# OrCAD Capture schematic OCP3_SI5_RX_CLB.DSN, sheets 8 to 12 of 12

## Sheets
8 PAGE08: size Custom
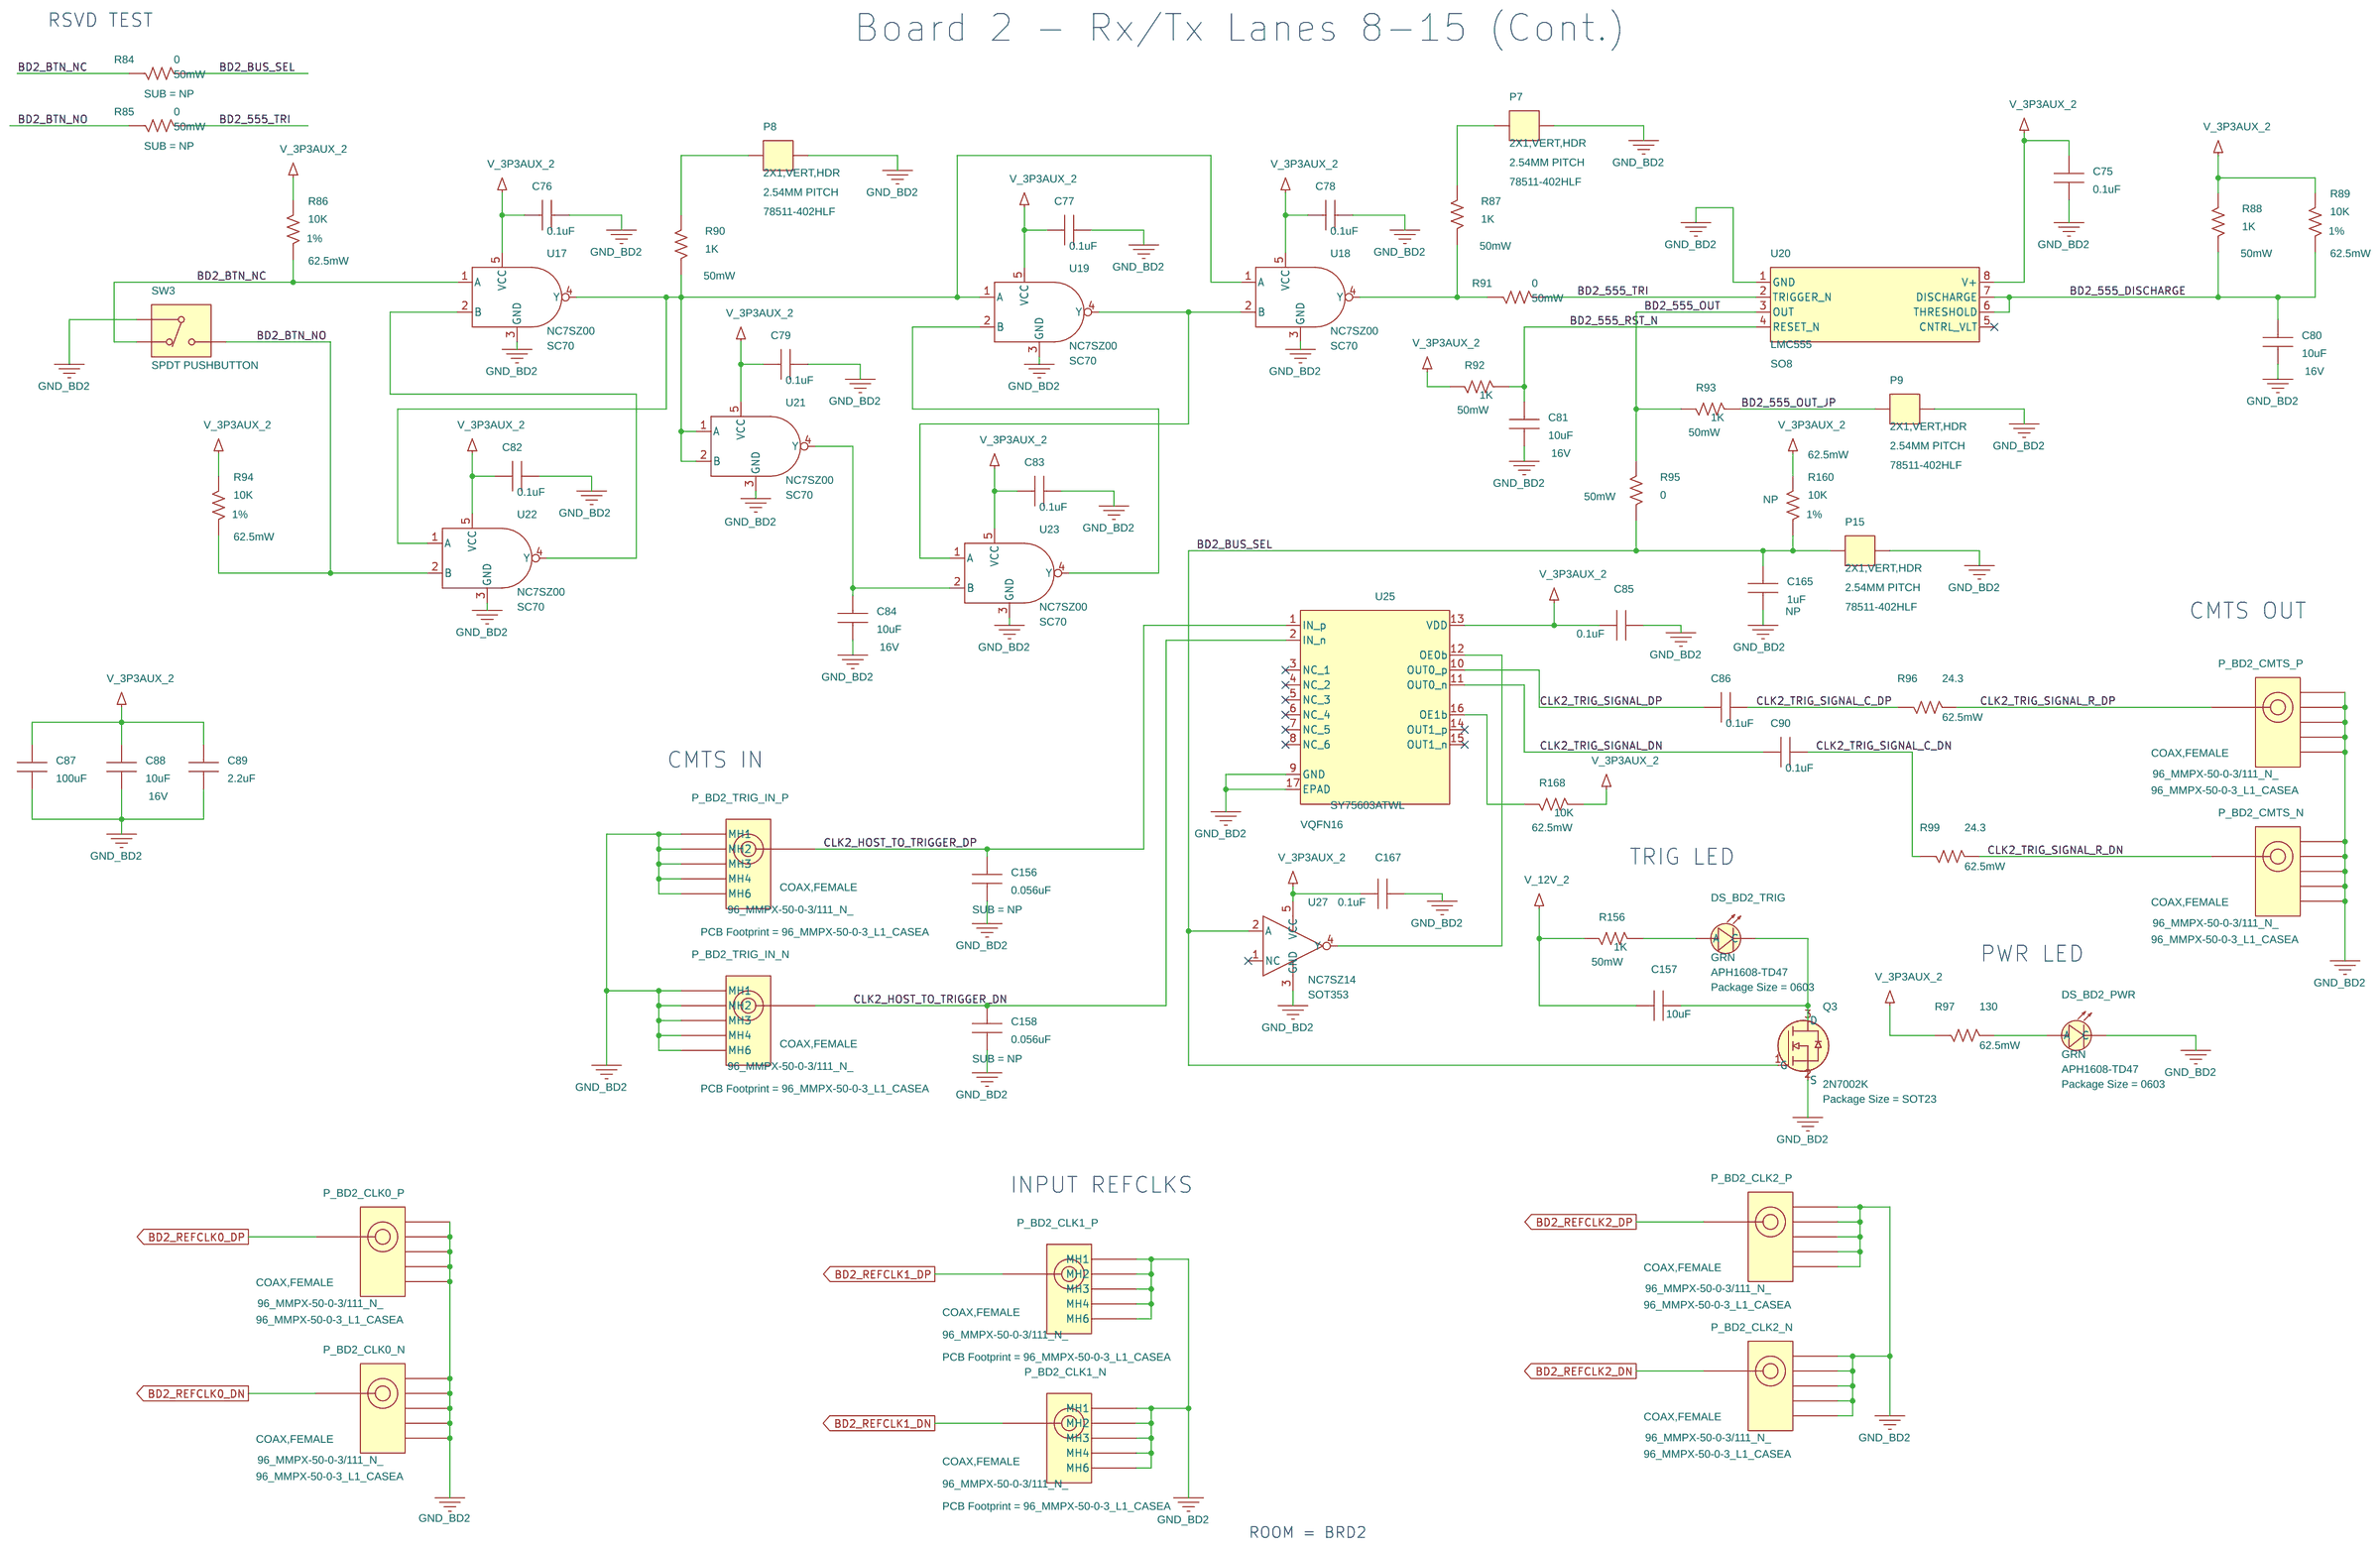
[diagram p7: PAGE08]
9 PAGE09: size Custom
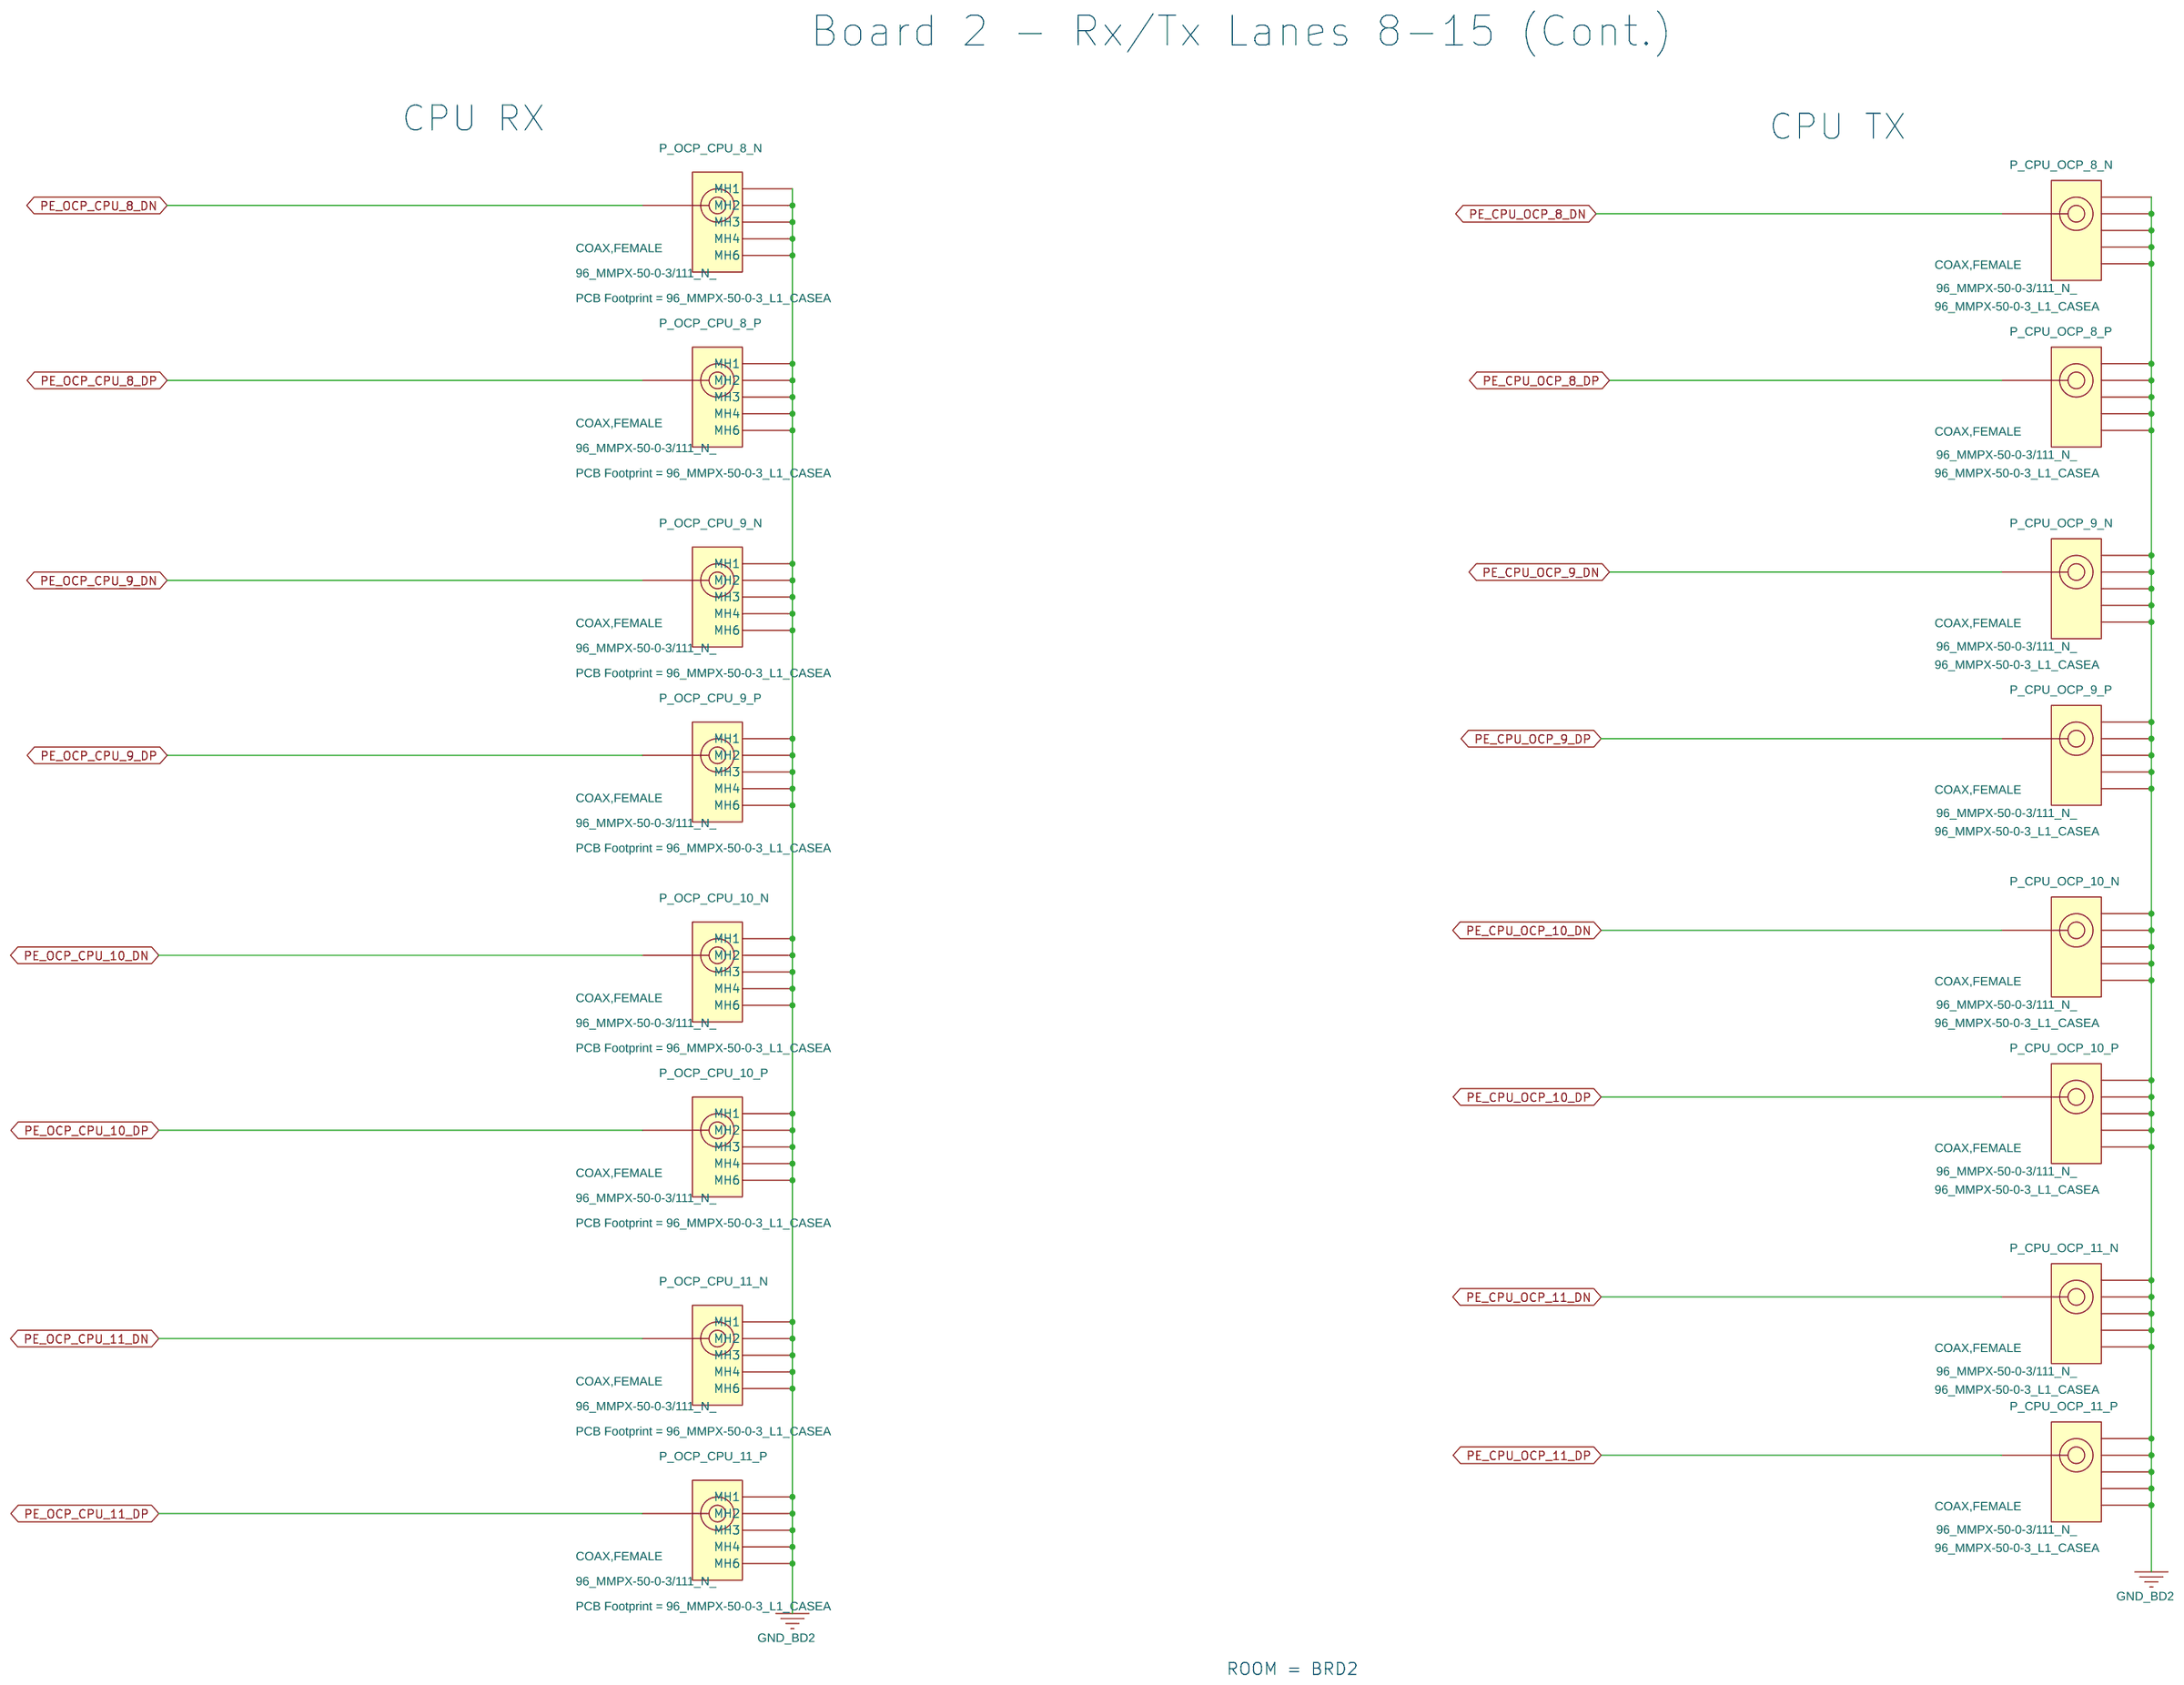
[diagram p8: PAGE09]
10 PAGE10: size Custom
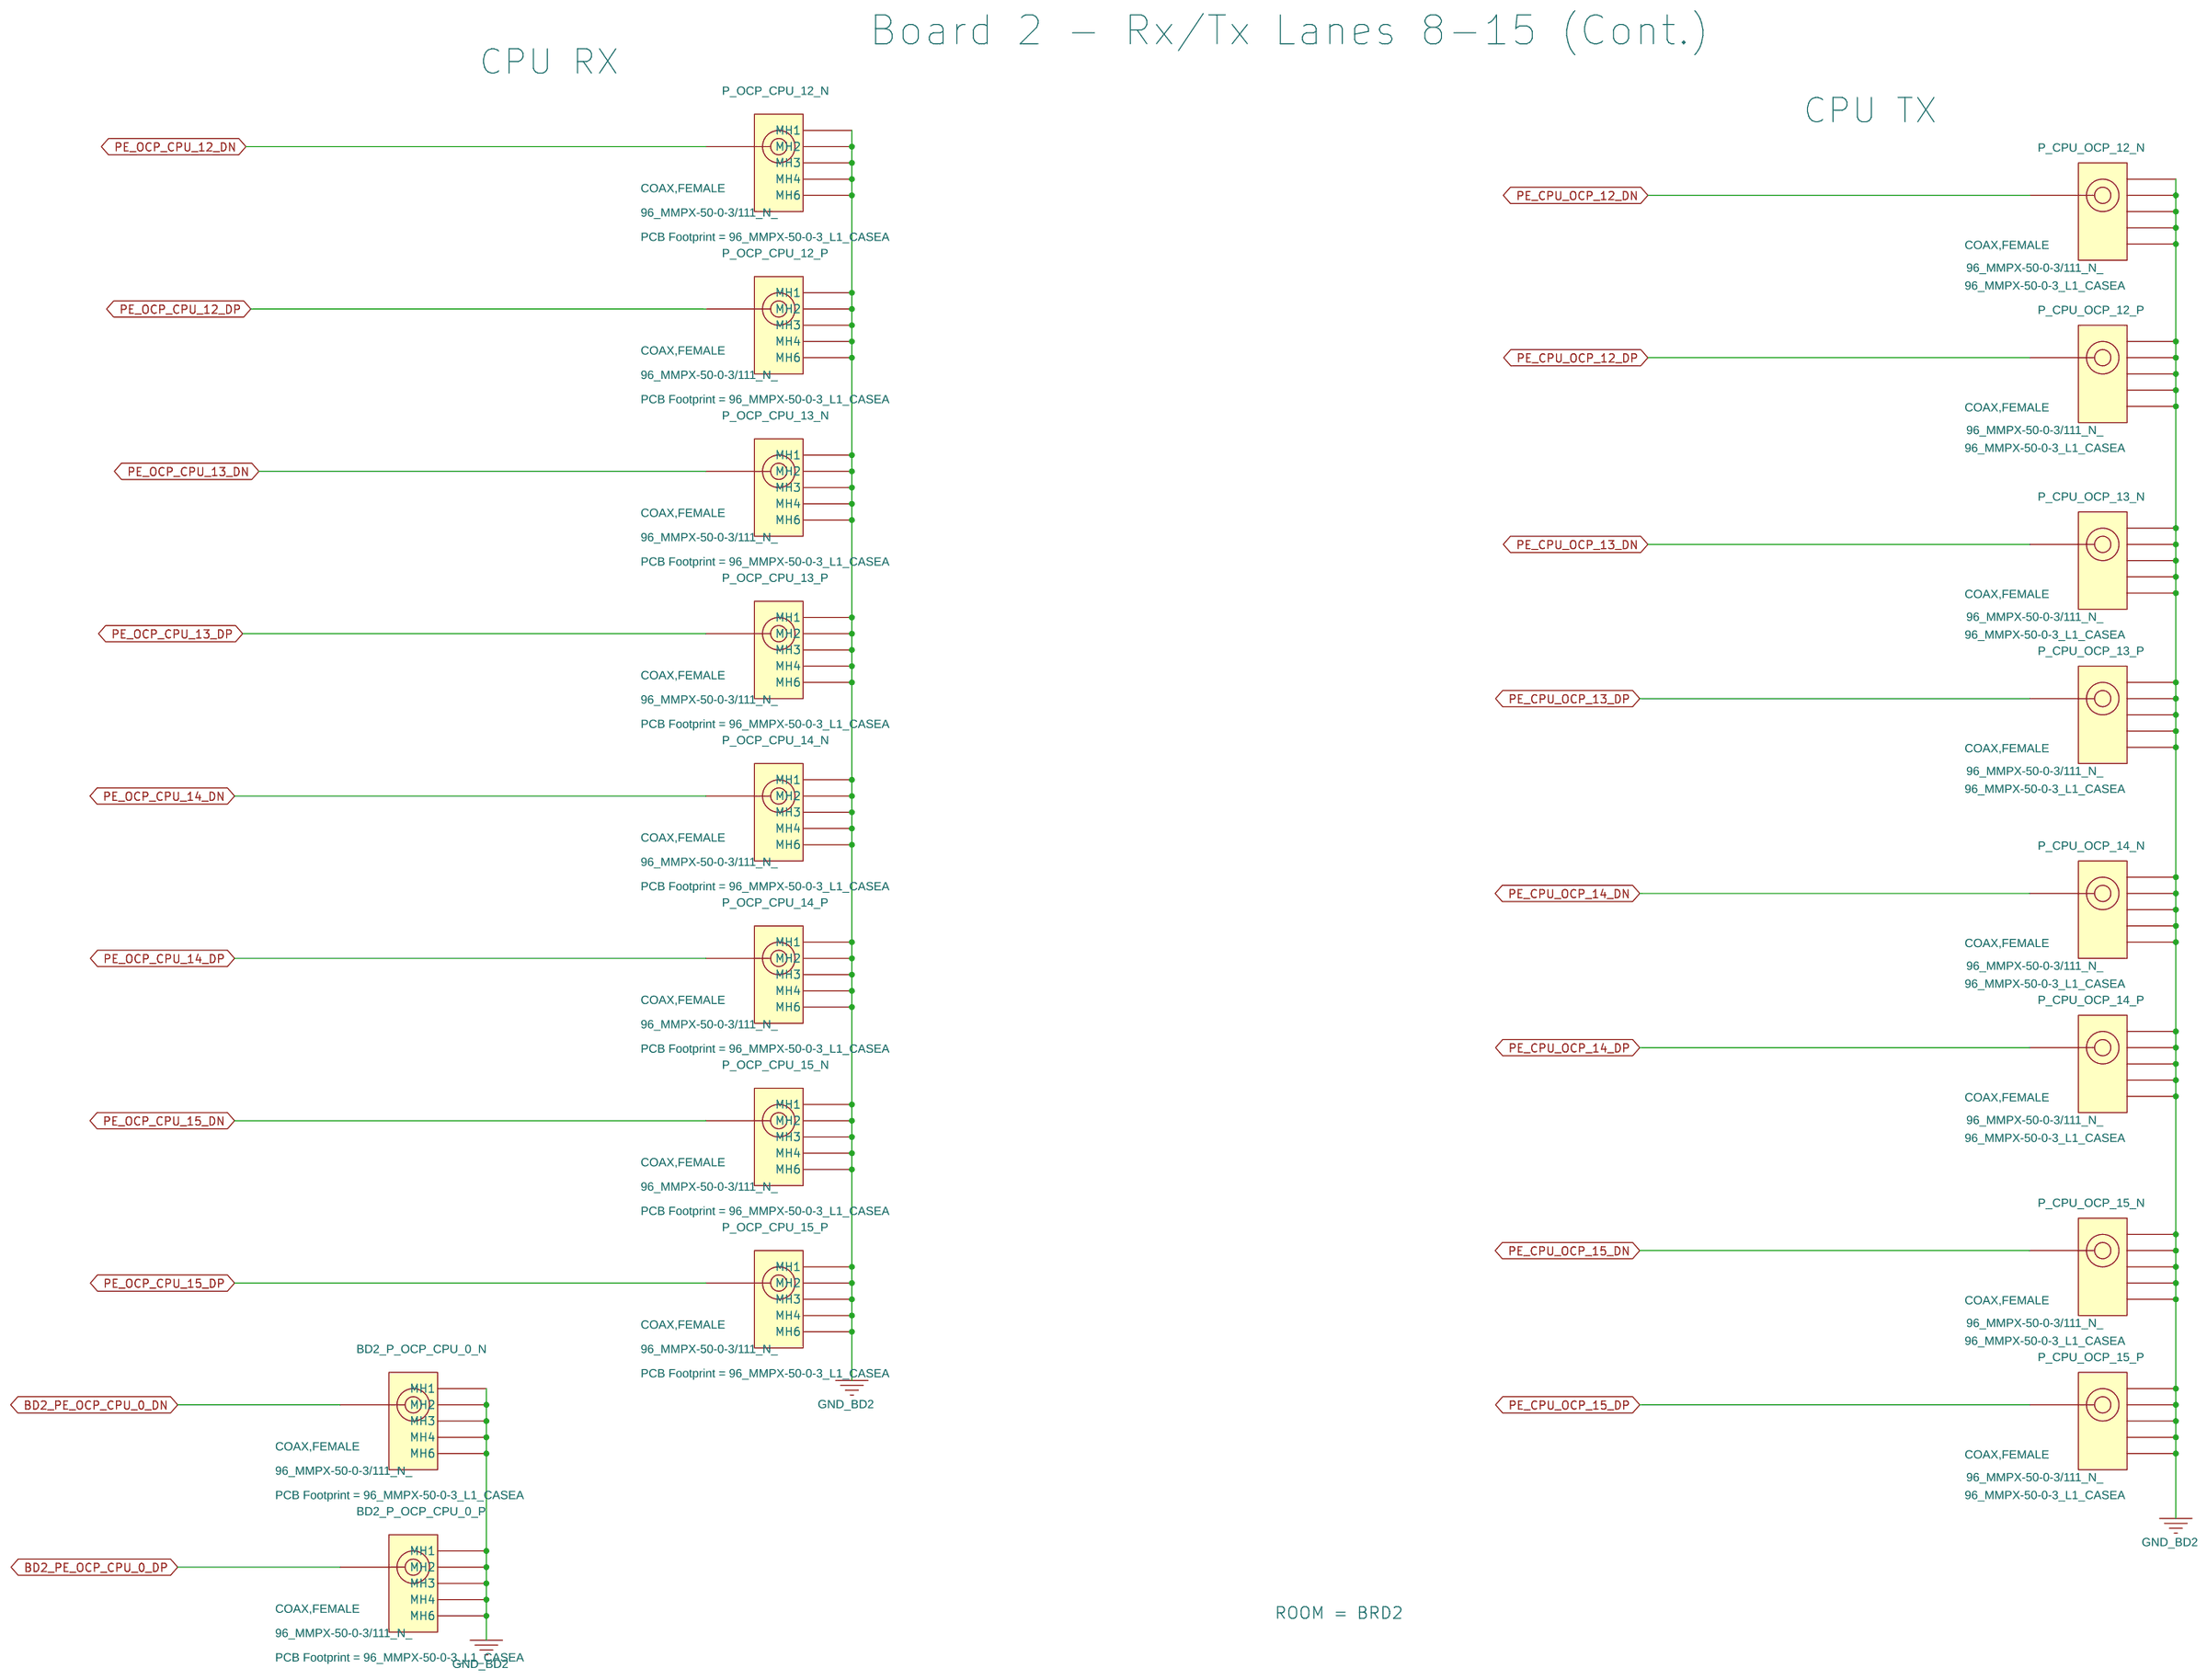
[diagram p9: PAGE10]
11 PAGE11: size Custom
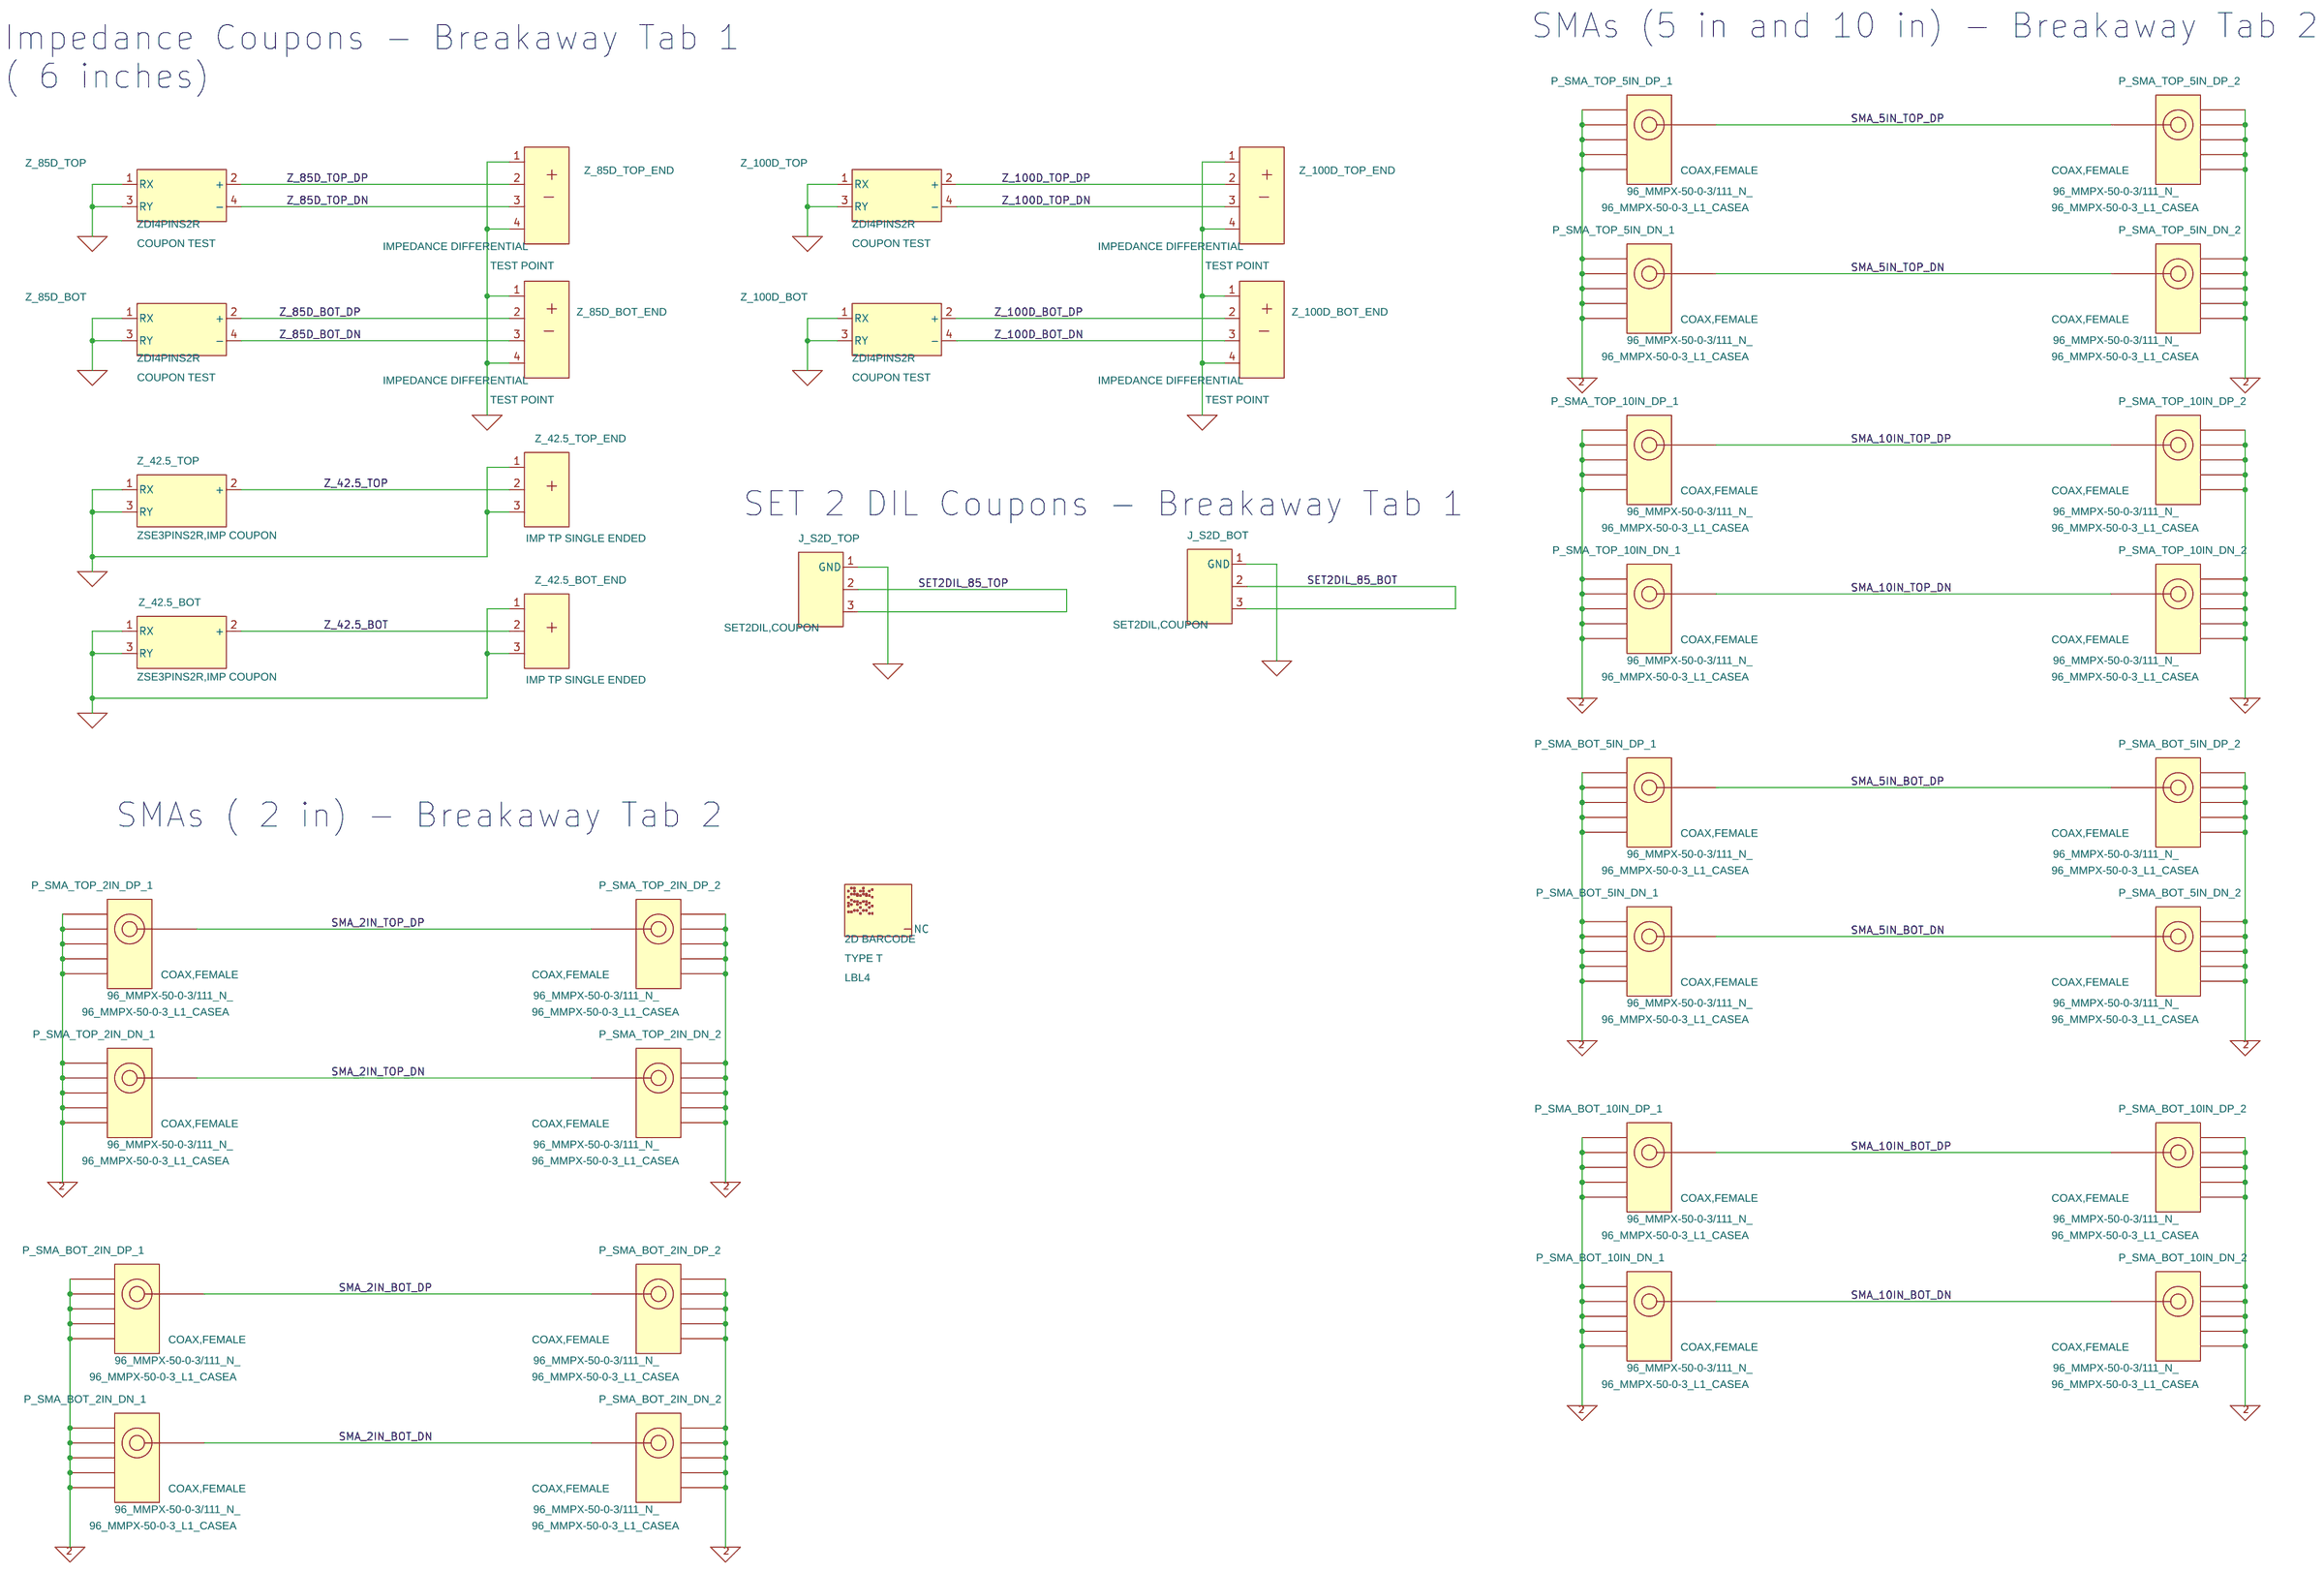
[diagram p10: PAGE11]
12 PAGE12: size Custom
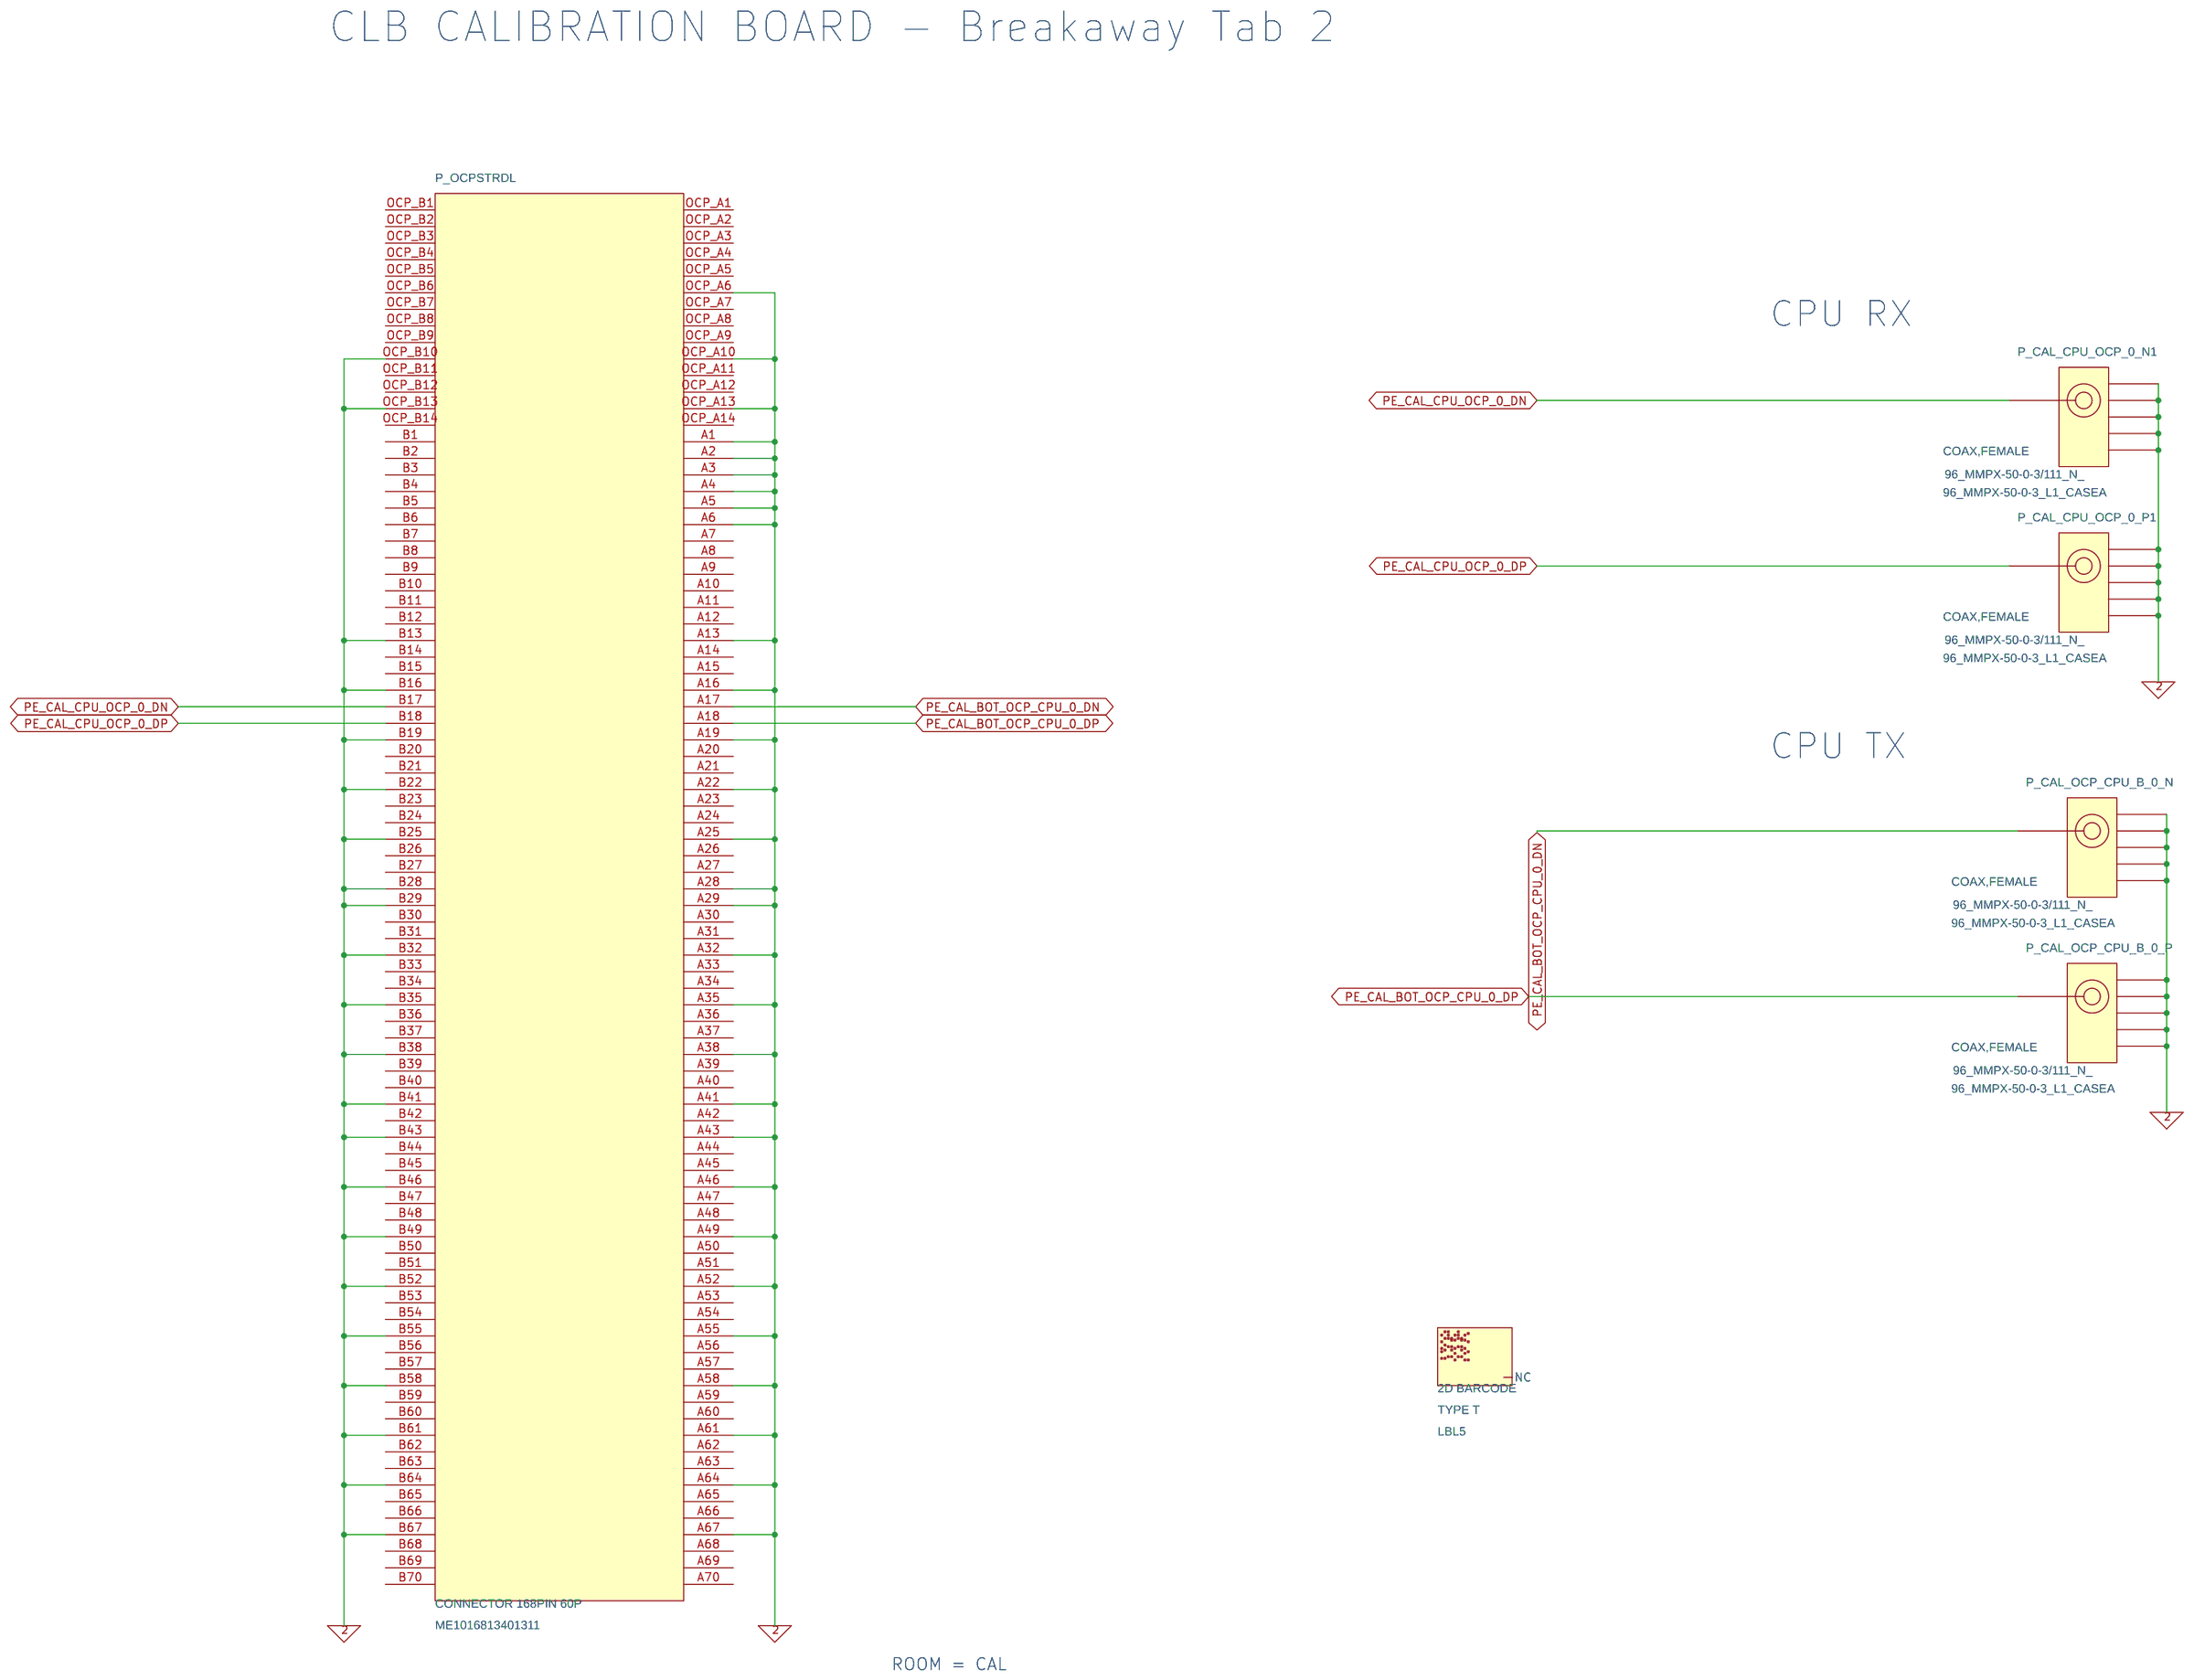
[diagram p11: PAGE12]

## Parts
sheet PAGE08
C75  0.1uF  [C0201]
C76  0.1uF  [C0201]
C77  0.1uF  [C0201]
C78  0.1uF  [C0201]
C79  0.1uF  [C0201]
C80  10uF  [C0603]
C81  10uF  [C0603]
C82  0.1uF  [C0201]
C83  0.1uF  [C0201]
C84  10uF  [C0603]
C85  0.1uF  [C0201]
C86  0.1uF  [C0201]
C87  100uF  [C1210_107H]
C88  10uF  [C0603]
C89  2.2uF  [C0603]
C90  0.1uF  [C0201]
C156  0.056uF  [C0402]
C157  10uF  [C0603]
C158  0.056uF  [C0402]
C165  1uF  [C0603]
C167  0.1uF  [C0201]
DS_BD2_PWR  APH1608-TD47  [LEDC1608X65N]
DS_BD2_TRIG  APH1608-TD47  [LEDC1608X65N]
P7  2X1,VERT,HDR  [BERG1X2]
P8  2X1,VERT,HDR  [BERG1X2]
P9  2X1,VERT,HDR  [BERG1X2]
P15  2X1,VERT,HDR  [BERG1X2]
P_BD2_CLK0_N  COAX,FEMALE  [96_MMPX-50-0-3_L1_CASEA]
P_BD2_CLK0_P  COAX,FEMALE  [96_MMPX-50-0-3_L1_CASEA]
P_BD2_CLK1_N  COAX,FEMALE  [96_MMPX-50-0-3_L1_CASEA]
P_BD2_CLK1_P  COAX,FEMALE  [96_MMPX-50-0-3_L1_CASEA]
P_BD2_CLK2_N  COAX,FEMALE  [96_MMPX-50-0-3_L1_CASEA]
P_BD2_CLK2_P  COAX,FEMALE  [96_MMPX-50-0-3_L1_CASEA]
P_BD2_CMTS_N  COAX,FEMALE  [96_MMPX-50-0-3_L1_CASEA]
P_BD2_CMTS_P  COAX,FEMALE  [96_MMPX-50-0-3_L1_CASEA]
P_BD2_TRIG_IN_N  COAX,FEMALE  [96_MMPX-50-0-3_L1_CASEA]
P_BD2_TRIG_IN_P  COAX,FEMALE  [96_MMPX-50-0-3_L1_CASEA]
Q3  2N7002K  [SOT95P237X117_3N]
R84  0  [R0201]
R85  0  [R0201]
R86  10K  [R0402]
R87  1K  [R0201]
R88  1K  [R0201]
R89  10K  [R0402]
R90  1K  [R0201]
R91  0  [R0201]
R92  1K  [R0201]
R93  1K  [R0201]
R94  10K  [R0402]
R95  0  [R0201]
R96  24.3  [R0402]
R97  130  [R0402]
R99  24.3  [R0402]
R156  1K  [R0201]
R160  10K  [R0402]
R168  10K  [R0402]
SW3  SPDT PUSHBUTTON  [SW3PSMRA_2SH]
U17  NC7SZ00  [SOT65P210X110_5N]
U18  NC7SZ00  [SOT65P210X110_5N]
U19  NC7SZ00  [SOT65P210X110_5N]
U20  LMC555  [SOIC127P600X175_8N]
U21  NC7SZ00  [SOT65P210X110_5N]
U22  NC7SZ00  [SOT65P210X110_5N]
U23  NC7SZ00  [SOT65P210X110_5N]
U25  SY75603ATWL  [QFN50P300X300X90-17]
U27  NC7SZ14  [SOT65P210X110_5L]
sheet PAGE09
P_CPU_OCP_8_N  COAX,FEMALE  [96_MMPX-50-0-3_L1_CASEA]
P_CPU_OCP_8_P  COAX,FEMALE  [96_MMPX-50-0-3_L1_CASEA]
P_CPU_OCP_9_N  COAX,FEMALE  [96_MMPX-50-0-3_L1_CASEA]
P_CPU_OCP_9_P  COAX,FEMALE  [96_MMPX-50-0-3_L1_CASEA]
P_CPU_OCP_10_N  COAX,FEMALE  [96_MMPX-50-0-3_L1_CASEA]
P_CPU_OCP_10_P  COAX,FEMALE  [96_MMPX-50-0-3_L1_CASEA]
P_CPU_OCP_11_N  COAX,FEMALE  [96_MMPX-50-0-3_L1_CASEA]
P_CPU_OCP_11_P  COAX,FEMALE  [96_MMPX-50-0-3_L1_CASEA]
P_OCP_CPU_8_N  COAX,FEMALE  [96_MMPX-50-0-3_L1_CASEA]
P_OCP_CPU_8_P  COAX,FEMALE  [96_MMPX-50-0-3_L1_CASEA]
P_OCP_CPU_9_N  COAX,FEMALE  [96_MMPX-50-0-3_L1_CASEA]
P_OCP_CPU_9_P  COAX,FEMALE  [96_MMPX-50-0-3_L1_CASEA]
P_OCP_CPU_10_N  COAX,FEMALE  [96_MMPX-50-0-3_L1_CASEA]
P_OCP_CPU_10_P  COAX,FEMALE  [96_MMPX-50-0-3_L1_CASEA]
P_OCP_CPU_11_N  COAX,FEMALE  [96_MMPX-50-0-3_L1_CASEA]
P_OCP_CPU_11_P  COAX,FEMALE  [96_MMPX-50-0-3_L1_CASEA]
sheet PAGE10
BD2_P_OCP_CPU_0_N  COAX,FEMALE  [96_MMPX-50-0-3_L1_CASEA]
BD2_P_OCP_CPU_0_P  COAX,FEMALE  [96_MMPX-50-0-3_L1_CASEA]
P_CPU_OCP_12_N  COAX,FEMALE  [96_MMPX-50-0-3_L1_CASEA]
P_CPU_OCP_12_P  COAX,FEMALE  [96_MMPX-50-0-3_L1_CASEA]
P_CPU_OCP_13_N  COAX,FEMALE  [96_MMPX-50-0-3_L1_CASEA]
P_CPU_OCP_13_P  COAX,FEMALE  [96_MMPX-50-0-3_L1_CASEA]
P_CPU_OCP_14_N  COAX,FEMALE  [96_MMPX-50-0-3_L1_CASEA]
P_CPU_OCP_14_P  COAX,FEMALE  [96_MMPX-50-0-3_L1_CASEA]
P_CPU_OCP_15_N  COAX,FEMALE  [96_MMPX-50-0-3_L1_CASEA]
P_CPU_OCP_15_P  COAX,FEMALE  [96_MMPX-50-0-3_L1_CASEA]
P_OCP_CPU_12_N  COAX,FEMALE  [96_MMPX-50-0-3_L1_CASEA]
P_OCP_CPU_12_P  COAX,FEMALE  [96_MMPX-50-0-3_L1_CASEA]
P_OCP_CPU_13_N  COAX,FEMALE  [96_MMPX-50-0-3_L1_CASEA]
P_OCP_CPU_13_P  COAX,FEMALE  [96_MMPX-50-0-3_L1_CASEA]
P_OCP_CPU_14_N  COAX,FEMALE  [96_MMPX-50-0-3_L1_CASEA]
P_OCP_CPU_14_P  COAX,FEMALE  [96_MMPX-50-0-3_L1_CASEA]
P_OCP_CPU_15_N  COAX,FEMALE  [96_MMPX-50-0-3_L1_CASEA]
P_OCP_CPU_15_P  COAX,FEMALE  [96_MMPX-50-0-3_L1_CASEA]
sheet PAGE11
J_S2D_BOT  SET2DIL,COUPON  [TP3_PPROBEB]
J_S2D_TOP  SET2DIL,COUPON  [TP3_PPROBEB]
LBL4  2d_label500x437  [2D_LABEL500X437]
P_SMA_BOT_2IN_DN_1  COAX,FEMALE  [96_MMPX-50-0-3_L1_CASEA]
P_SMA_BOT_2IN_DN_2  COAX,FEMALE  [96_MMPX-50-0-3_L1_CASEA]
P_SMA_BOT_2IN_DP_1  COAX,FEMALE  [96_MMPX-50-0-3_L1_CASEA]
P_SMA_BOT_2IN_DP_2  COAX,FEMALE  [96_MMPX-50-0-3_L1_CASEA]
P_SMA_BOT_5IN_DN_1  COAX,FEMALE  [96_MMPX-50-0-3_L1_CASEA]
P_SMA_BOT_5IN_DN_2  COAX,FEMALE  [96_MMPX-50-0-3_L1_CASEA]
P_SMA_BOT_5IN_DP_1  COAX,FEMALE  [96_MMPX-50-0-3_L1_CASEA]
P_SMA_BOT_5IN_DP_2  COAX,FEMALE  [96_MMPX-50-0-3_L1_CASEA]
P_SMA_BOT_10IN_DN_1  COAX,FEMALE  [96_MMPX-50-0-3_L1_CASEA]
P_SMA_BOT_10IN_DN_2  COAX,FEMALE  [96_MMPX-50-0-3_L1_CASEA]
P_SMA_BOT_10IN_DP_1  COAX,FEMALE  [96_MMPX-50-0-3_L1_CASEA]
P_SMA_BOT_10IN_DP_2  COAX,FEMALE  [96_MMPX-50-0-3_L1_CASEA]
P_SMA_TOP_2IN_DN_1  COAX,FEMALE  [96_MMPX-50-0-3_L1_CASEA]
P_SMA_TOP_2IN_DN_2  COAX,FEMALE  [96_MMPX-50-0-3_L1_CASEA]
P_SMA_TOP_2IN_DP_1  COAX,FEMALE  [96_MMPX-50-0-3_L1_CASEA]
P_SMA_TOP_2IN_DP_2  COAX,FEMALE  [96_MMPX-50-0-3_L1_CASEA]
P_SMA_TOP_5IN_DN_1  COAX,FEMALE  [96_MMPX-50-0-3_L1_CASEA]
P_SMA_TOP_5IN_DN_2  COAX,FEMALE  [96_MMPX-50-0-3_L1_CASEA]
P_SMA_TOP_5IN_DP_1  COAX,FEMALE  [96_MMPX-50-0-3_L1_CASEA]
P_SMA_TOP_5IN_DP_2  COAX,FEMALE  [96_MMPX-50-0-3_L1_CASEA]
P_SMA_TOP_10IN_DN_1  COAX,FEMALE  [96_MMPX-50-0-3_L1_CASEA]
P_SMA_TOP_10IN_DN_2  COAX,FEMALE  [96_MMPX-50-0-3_L1_CASEA]
P_SMA_TOP_10IN_DP_1  COAX,FEMALE  [96_MMPX-50-0-3_L1_CASEA]
P_SMA_TOP_10IN_DP_2  COAX,FEMALE  [96_MMPX-50-0-3_L1_CASEA]
Z_42.5_BOT  ZSE3PINS2R,IMP COUPON  [ZSE3PINS2R]
Z_42.5_BOT_END  IMP TP SINGLE ENDED  [IMP_TP_1X3_35P]
Z_42.5_TOP  ZSE3PINS2R,IMP COUPON  [ZSE3PINS2R]
Z_42.5_TOP_END  IMP TP SINGLE ENDED  [IMP_TP_1X3_35P]
Z_85D_BOT  zdi4pins2r  [ZDI4PINS2R]
Z_85D_BOT_END  imp_tp_diff  [IMP_TP_1X4_35P]
Z_85D_TOP  zdi4pins2r  [ZDI4PINS2R]
Z_85D_TOP_END  imp_tp_diff  [IMP_TP_1X4_35P]
Z_100D_BOT  zdi4pins2r  [ZDI4PINS2R]
Z_100D_BOT_END  imp_tp_diff  [IMP_TP_1X4_35P]
Z_100D_TOP  zdi4pins2r  [ZDI4PINS2R]
Z_100D_TOP_END  imp_tp_diff  [IMP_TP_1X4_35P]
sheet PAGE12
LBL5  2d_label500x437  [2D_LABEL500X437]
P_CAL_CPU_OCP_0_N1  COAX,FEMALE  [96_MMPX-50-0-3_L1_CASEA]
P_CAL_CPU_OCP_0_P1  COAX,FEMALE  [96_MMPX-50-0-3_L1_CASEA]
P_CAL_OCP_CPU_B_0_N  COAX,FEMALE  [96_MMPX-50-0-3_L1_CASEA]
P_CAL_OCP_CPU_B_0_P  COAX,FEMALE  [96_MMPX-50-0-3_L1_CASEA]
P_OCPSTRDL  CONNECTOR 168PIN 60P  [AMP_STRDL_168PIN_60P]

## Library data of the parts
C75-C79 C82 C83 C85 C86 C90 C167 = cap: CAP,0.1UF,10%,10V,X5R,0201; ALT_SYMBOLS: (CAPC0603X33N,C0201M_FOX,C0201_R4); CLASS: DISCRETE; DPN: MNN3J; Dielectric Type: X5R; Lead Free: Yes; Lifecycle Phase: A Revision; Manufacturer: DARFON ELECTRONICS CORP; Manufacturer PN: C0603X5R104KDT; Package Height: 0.33 MM; Package Size: 0201; Package Type: SMD; Part Number: MNN3J; ROOM: BRD2; Rev: A00-00; Tolerance: 10%; Voltage: 10V
C80 C81 C84 C88 = cap: CAP,10UF,20%,16V,X6S,0603; CLASS: DISCRETE; DEVICE: 090729120217; DPN: 3MRV8; Dielectric Type: X6S; Lead Free: Yes; Lifecycle Phase: A Revision; Manufacturer: MURATA ERIE; Manufacturer PN: GRM188C81C106MA73D; Package Height: 40 MIL; Package Size: 0603; Package Type: SMD; Part Number: 3MRV8; ROOM: BRD2; Rev: A00-00; TOLERANCE: 20%; VOLTAGE: 16V
C87 = cap: CAP,100UF,20%,6.3V,X5R,1210; CLASS: DISCRETE; DPN: DN761; Dielectric Type: X5R; Lead Free: Yes; Lifecycle Phase: A Revision; Manufacturer: MURATA ERIE; Manufacturer PN: GRM32ER60J107ME20L; Package Height: 107 MIL; Package Size: 1210; Package Type: SMD; Part Number: DN761; ROOM: BRD2; Rev: A00-00; Tolerance: 20%; Voltage: 6.3V
C89 = cap: CAP,2.2UF,10%,16V,X5R,0603; CLASS: DISCRETE; DPN: J6201; Dielectric Type: X5R; Lead Free: Yes; Lifecycle Phase: A Revision; Manufacturer: MURATA ERIE; Manufacturer PN: GRM188R61C225KE15D; Package Height: 40 MIL; Package Size: 0603; Package Type: SMD; Part Number: J6201; ROOM: BRD2; Rev: A00-00; Tolerance: 10%; Voltage: 16V
C156 C158 = cap: CAP,0.056UF,10%,10V,X7R,0402; CLASS: DISCRETE; DPN: KN9YT; Dielectric Type: X7R; Lead Free: Yes; Lifecycle Phase: Preliminary; Manufacturer: SAMSUNG; Manufacturer PN: CL05B563KP5NNNC; Package Height: 24 MIL; Package Size: 0402; Package Type: SMD; Part Number: KN9YT; ROOM: BRD2; Rev: Introductory; SUB: NP; Tolerance: 10%; Voltage: 10V
C157 = cap: CAP,10UF,20%,16V,X6S,0603; CLASS: DISCRETE; DPN: 3MRV8; Dielectric Type: X6S; Lead Free: Yes; Lifecycle Phase: A Revision; Manufacturer: MURATA ERIE; Manufacturer PN: GRM188C81C106MA73D; Package Height: 40 MIL; Package Size: 0603; Package Type: SMD; Part Number: 3MRV8; ROOM: BRD2; Rev: A00-00; Tolerance: 20%; Voltage: 16V
C165 = cap: CAP,1UF,10%,16V,X7R,0603; CLASS: DISCRETE; DPN: RY497; Dielectric Type: X7R; Lead Free: Yes; Lifecycle Phase: A Revision; Manufacturer: KEMET ELECTRONICS; Manufacturer PN: C0603C105K4RAC; Package Height: 40 MIL; Package Size: 0603; Package Type: SMD; Part Number: RY497; ROOM: BRD2; Rev: A00-00; SUB: NP; Tolerance: 10%; Voltage: 16V
DS_BD2_PWR DS_BD2_TRIG = g_led_a1_c2: LED,0603,CLR,GRN,2V,20MA,35MCD; CLASS: DISCRETE; DPN: UJ387; LED Color: GRN; Lead Free: Yes; Lifecycle Phase: A Revision; Manufacturer: KINGBRIGHT CORPORATION; Package Height: 0.65 MM; Package Size: 0603; Package Type: SMD; Part Number: UJ387; ROOM: BRD2; Rev: A01-00; Voltage: 2V
P7-P9 P15 = g_2x1: CON,HDR,1X2,M,.1X.32,S,T,U,TH; CLASS: IO; DPN: RD013; Lead Free: Yes; Lifecycle Phase: A Revision; Manufacturer: FCI; Manufacturer PN: 78511-402HLF; Package Height: 426 MIL; Package Size: HDR1X2; Package Type: TH; Part Number: RD013; Pin Info: 2.54MM PITCH; ROOM: BRD2; Rev: A00-00
P_BD2_CLK0_N P_BD2_CLK0_P P_BD2_CLK2_N P_BD2_CLK2_P P_BD2_CMTS_N P_BD2_CMTS_P P_CAL_CPU_OCP_0_N1 P_CAL_CPU_OCP_0_P1 P_CAL_OCP_CPU_B_0_N P_CAL_OCP_CPU_B_0_P P_CPU_OCP_8_N P_CPU_OCP_8_P P_CPU_OCP_9_N P_CPU_OCP_9_P P_CPU_OCP_10_N P_CPU_OCP_10_P P_CPU_OCP_11_N P_CPU_OCP_11_P P_CPU_OCP_12_N P_CPU_OCP_12_P P_CPU_OCP_13_N P_CPU_OCP_13_P P_CPU_OCP_14_N P_CPU_OCP_14_P P_CPU_OCP_15_N P_CPU_OCP_15_P P_SMA_BOT_2IN_DN_1 P_SMA_BOT_2IN_DN_2 P_SMA_BOT_2IN_DP_1 P_SMA_BOT_2IN_DP_2 P_SMA_BOT_5IN_DN_1 P_SMA_BOT_5IN_DN_2 P_SMA_BOT_5IN_DP_1 P_SMA_BOT_5IN_DP_2 P_SMA_BOT_10IN_DN_1 P_SMA_BOT_10IN_DN_2 P_SMA_BOT_10IN_DP_1 P_SMA_BOT_10IN_DP_2 P_SMA_TOP_2IN_DN_1 P_SMA_TOP_2IN_DN_2 P_SMA_TOP_2IN_DP_1 P_SMA_TOP_2IN_DP_2 P_SMA_TOP_5IN_DN_1 P_SMA_TOP_5IN_DN_2 P_SMA_TOP_5IN_DP_1 P_SMA_TOP_5IN_DP_2 P_SMA_TOP_10IN_DN_1 P_SMA_TOP_10IN_DN_2 P_SMA_TOP_10IN_DP_1 P_SMA_TOP_10IN_DP_2 = g_jack_0: CON,HDR,COAXIAL,F,G,SMT; ALT_SYMBOLS: (96_mmpx-50-0-3_l6_casea); Manufacturer: HUBBLE INC; Manufacturer PN: 96_MMPX-50-0-3/111_N_; Package Height: 247 MIL; Package Type: SMD/TH; Part Number: 50Y9H
BD2_P_OCP_CPU_0_N BD2_P_OCP_CPU_0_P P_BD2_CLK1_N P_BD2_CLK1_P P_BD2_TRIG_IN_N P_BD2_TRIG_IN_P P_OCP_CPU_8_N P_OCP_CPU_8_P P_OCP_CPU_9_N P_OCP_CPU_9_P P_OCP_CPU_10_N P_OCP_CPU_10_P P_OCP_CPU_11_N P_OCP_CPU_11_P P_OCP_CPU_12_N P_OCP_CPU_12_P P_OCP_CPU_13_N P_OCP_CPU_13_P P_OCP_CPU_14_N P_OCP_CPU_14_P P_OCP_CPU_15_N P_OCP_CPU_15_P = g_jack_1: CON,HDR,COAXIAL,F,G,SMT; ALT_SYMBOLS: (96_mmpx-50-0-3_l6_casea); DPN: WD7FW; Lead Free: Yes; Lifecycle Phase: Preliminary; Manufacturer: HUBBLE INC; Manufacturer PN: 96_MMPX-50-0-3/111_N_; Package Height: 247 MIL; Package Type: SMD/TH; Part Number: 50Y9H; ROOM: BRD1; Rev: Introductory
Q3 = ft2n7002k_sot23: TRANS,FET,NCHN,60V,SOT23,ESD1K; CLASS: DISCRETE; DPN: FR033; Lead Free: Yes; Lifecycle Phase: A Revision; Manufacturer: NXP SEMICONDUCTOR; Package Height: 1.17 MM; Package Size: SOT23; Package Type: SMD; Part Number: FR033; Polarity: N-Channel; ROOM: BRD2; Rated Voltage: 60V; Rev: A00-00
R84 R85 = res: RES,0,1/20W,5%,THKFLM,0201; ALT_SYMBOLS: (R0201_R4,R0201M_FOX); CLASS: DISCRETE; DPN: YY941; Lead Free: Yes; Lifecycle Phase: A Revision; Manufacturer: KOA; Manufacturer PN: RK73Z1HTQTC; Material: Thick Film; Package Height: 0.33 MM; Package Size: 0201; Package Type: SMD; Part Number: YY941; ROOM: BRD2; Rated Power: 50mW; Rev: A00-00; SUB: NP; Tolerance: 5%
R86 R89 R94 = res: RES,10K,1/16W,1%,THKFLM,0402; DEVICE: 090729121122; Part Number: N1256; ROOM: BRD2; Rated Power: 62.5mW; TOLERANCE: 1%
R87 R88 R90 R92 R93 R156 = res: RES,1K,1/20W,1%,THKFLM,0201; ALT_SYMBOLS: (R0201_R4,R0201M_FOX); CLASS: DISCRETE; DPN: 3WWMJ; Lead Free: Yes; Lifecycle Phase: A Revision; Manufacturer: KOA; Manufacturer PN: RK73H1HTQTC1001F; Material: Thick Film; Package Height: 0.33 MM; Package Size: 0201; Package Type: SMD; Part Number: 3WWMJ; ROOM: BRD2; Rated Power: 50mW; Rev: A00-00; Tolerance: 1%
R91 R95 = res: RES,0,1/20W,5%,THKFLM,0201; ALT_SYMBOLS: (R0201_R4,R0201M_FOX); CLASS: DISCRETE; DPN: YY941; Lead Free: Yes; Lifecycle Phase: A Revision; Manufacturer: KOA; Manufacturer PN: RK73Z1HTQTC; Material: Thick Film; Package Height: 0.33 MM; Package Size: 0201; Package Type: SMD; Part Number: YY941; ROOM: BRD2; Rated Power: 50mW; Rev: A00-00; Tolerance: 5%
R96 R99 = res: RES,24.3,1/16W,1%,THKFLM,0402; CLASS: DISCRETE; DPN: H8992; Lead Free: Yes; Lifecycle Phase: A Revision; Manufacturer: KOA; Manufacturer PN: RK73H1ET-24R3F; Material: Thick Film; Package Height: 16 MIL; Package Size: 0402; Package Type: SMD; Part Number: H8992; ROOM: BRD2; Rated Power: 62.5mW; Rev: A00-00; Tolerance: 1%
R97 = res: RES,130,1/16W,1%,THKFLM,0402; CLASS: DISCRETE; DPN: J8387; Lead Free: Yes; Lifecycle Phase: A Revision; Manufacturer: KOA; Manufacturer PN: RK73H1ETTP1300F; Material: Thick Film; Package Height: 16 MIL; Package Size: 0402; Package Type: SMD; Part Number: J8387; ROOM: BRD2; Rated Power: 62.5mW; Rev: A00-00; Tolerance: 1%
R160 = res: RES,10K,1/16W,1%,THKFLM,0402; DEVICE: 090729121122; Part Number: N1256; ROOM: BRD2; Rated Power: 62.5mW; SUB: NP; TOLERANCE: 1%
R168 = res: RES,10K,1/16W,1%,THKFLM,0402; CLASS: DISCRETE; DPN: 3WWMJ; Lead Free: Yes; Lifecycle Phase: A Revision; Manufacturer: KOA; Manufacturer PN: RK73H1ETTP1002F; Material: Thick Film; Package Height: 16 MIL; Package Size: 0402; Package Type: SMD; Part Number: N1256; ROOM: BRD1; Rated Power: 62.5mW; Rev: A00-00; Tolerance: 1%
SW3 = sw3psmra_spdt: SWT,PB,SPDT,ON-MOM,SMT; CLASS: DISCRETE; DPN: GC8VG; Lead Free: Yes; Lifecycle Phase: X Revision; Manufacturer: C&K; Manufacturer PN: EP12SD1SAPE; Package Height: 5.08 MM; Package Type: SMD; Part Number: GC8VG; ROOM: BRD2; Rev: X00-00; Switch Configuration: SPDT; Switch Type: PUSHBUTTON
U17-U19 U21-U23 = g_nand_1slot_a1_b2: IC,NC7SZ00,SC70,2-INPUT-NAND; CLASS: IC; DPN: RPWR7; Lead Free: Yes; Lifecycle Phase: A Revision; Manufacturer: FAIRCHILD; Manufacturer PN: NC7SZ00P5X; Package Height: 1.1 MM; Package Size: SC70; Package Type: SMD; Part Number: RPWR7; ROOM: BRD2; Rev: A00-00
U20 = lmc555: IC,C555,SO8,CMOS TIMER; CLASS: IC; DPN: 83011; Lead Free: No; Lifecycle Phase: A Revision; Manufacturer: NATIONAL SEMICONDUCTOR; Manufacturer PN: LMC555CM; Package Height: 1.75 MM; Package Size: SO8; Package Type: SMD; Part Number: 83011; ROOM: BRD2; Rev: A00-00
U25 = SY75603ATWL: IC,PCEI CLKBUFF,2OUTPUT,VQFN16; Manufacturer: MICROCHIP TECHNOLOGY INC.; Package Height: 0.9 MM; Package Size: VQFN16; Package Type: SMD; Part Number: PVWXM
U27 = g_inv_1slot_nc1_a2: IC,7SZ14,SOT353,INVERTER; CLASS: IC; Manufacturer: FAIRCHILD; Manufacturer PN: NC7SZ14P5X; Package Height: 1.1 MM; Package Size: SOT353; Package Type: SMD; Part Number: DT962
J_S2D_BOT J_S2D_TOP = tp3_pprobeb_sm-empty: PROBE,3-PIN,SMT,W/ALIGN PINS; BOM_IGNORE: TRUE; CLASS: DISCRETE; DPN: 00000; Lead Free: N/A; Lifecycle Phase: N/A; Package Height: 10 MIL; Package Type: SMD; Part Number: 110408130004; Rev: N/A
LBL4 LBL5 = 2d_label500x437: LABEL,2D BARCODE,.500X.437,TYPE T; DEVICE: 090730100102; Part Number: HP126; ROOM: BRD2; TAG1: 2D BARCODE; TAG2: TYPE T
Z_42.5_BOT Z_42.5_TOP = zse3pins2r: IMPEDENCE COUPON 3 PIN; BOM_IGNORE: TRUE; CLASS: DISCRETE; DPN: 00000; Lead Free: N/A; Lifecycle Phase: N/A; Package Height: 1 MIL; Package Type: TH; Part Number: 090730100157; Rev: N/A
Z_42.5_BOT_END Z_42.5_TOP_END = imp_tp_se: IMPEDENCE TEST POINT 25RD12 SINGLE ENDED 1X3; BOM_IGNORE: TRUE; CLASS: DISCRETE; DPN: 00000; Lead Free: N/A; Lifecycle Phase: N/A; Package Height: 1 MIL; Package Type: TH; Part Number: 090730100116; Rev: N/A
Z_85D_BOT Z_85D_TOP Z_100D_BOT Z_100D_TOP = zdi4pins2r: IMPEDENCE COUPON 4 PIN; DEVICE: 090730100156; Part Number: 00000; TAG2: COUPON TEST
Z_85D_BOT_END Z_85D_TOP_END Z_100D_BOT_END Z_100D_TOP_END = imp_tp_diff: IMPEDENCE TEST POINT 25RD12 DIFFERENTIAL 1X4; DEVICE: 090730100117; Part Number: 00000; TAG1: IMPEDANCE DIFFERENTIAL; TAG2: TEST POINT
P_OCPSTRDL = c84edg_amp: CON,EC,168,.6MM,S,G,ST; CLASS: IO; DPN: 7HYMF; Lead Free: Yes; Lifecycle Phase: X Revision; Manufacturer: AMPHENOL; Manufacturer PN: ME1016813401311; Package Height: 6 MM; Package Type: SMD; Part Number: 7HYMF; Rev: X00-00

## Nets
AGND_2: P_CAL_CPU_OCP_0_N1.2 P_CAL_CPU_OCP_0_N1.3 P_CAL_CPU_OCP_0_N1.4 P_CAL_CPU_OCP_0_N1.5 P_CAL_CPU_OCP_0_N1.6 P_CAL_CPU_OCP_0_P1.2 P_CAL_CPU_OCP_0_P1.3 P_CAL_CPU_OCP_0_P1.4 P_CAL_CPU_OCP_0_P1.5 P_CAL_CPU_OCP_0_P1.6 P_CAL_OCP_CPU_B_0_N.2 P_CAL_OCP_CPU_B_0_N.3 P_CAL_OCP_CPU_B_0_N.4 P_CAL_OCP_CPU_B_0_N.5 P_CAL_OCP_CPU_B_0_N.6 P_CAL_OCP_CPU_B_0_P.2 P_CAL_OCP_CPU_B_0_P.3 P_CAL_OCP_CPU_B_0_P.4 P_CAL_OCP_CPU_B_0_P.5 P_CAL_OCP_CPU_B_0_P.6 P_OCPSTRDL.A1 P_OCPSTRDL.A2 P_OCPSTRDL.A3 P_OCPSTRDL.A4 P_OCPSTRDL.A5 P_OCPSTRDL.A6 P_OCPSTRDL.A13 P_OCPSTRDL.A16 P_OCPSTRDL.A19 P_OCPSTRDL.A22 P_OCPSTRDL.A25 P_OCPSTRDL.A28 P_OCPSTRDL.A29 P_OCPSTRDL.A32 P_OCPSTRDL.A35 P_OCPSTRDL.A38 P_OCPSTRDL.A41 P_OCPSTRDL.A43 P_OCPSTRDL.A46 P_OCPSTRDL.A49 P_OCPSTRDL.A52 P_OCPSTRDL.A55 P_OCPSTRDL.A58 P_OCPSTRDL.A61 P_OCPSTRDL.A64 P_OCPSTRDL.A67 P_OCPSTRDL.B13 P_OCPSTRDL.B16 P_OCPSTRDL.B19 P_OCPSTRDL.B22 P_OCPSTRDL.B25 P_OCPSTRDL.B28 P_OCPSTRDL.B29 P_OCPSTRDL.B32 P_OCPSTRDL.B35 P_OCPSTRDL.B38 P_OCPSTRDL.B41 P_OCPSTRDL.B43 P_OCPSTRDL.B46 P_OCPSTRDL.B49 P_OCPSTRDL.B52 P_OCPSTRDL.B55 P_OCPSTRDL.B58 P_OCPSTRDL.B61 P_OCPSTRDL.B64 P_OCPSTRDL.B67 P_OCPSTRDL.OCP_A6 P_OCPSTRDL.OCP_A10 P_OCPSTRDL.OCP_A13 P_OCPSTRDL.OCP_B10 P_OCPSTRDL.OCP_B13 P_SMA_BOT_2IN_DN_1.2 P_SMA_BOT_2IN_DN_1.3 P_SMA_BOT_2IN_DN_1.4 P_SMA_BOT_2IN_DN_1.5 P_SMA_BOT_2IN_DN_1.6 P_SMA_BOT_2IN_DN_2.2 P_SMA_BOT_2IN_DN_2.3 P_SMA_BOT_2IN_DN_2.4 P_SMA_BOT_2IN_DN_2.5 P_SMA_BOT_2IN_DN_2.6 P_SMA_BOT_2IN_DP_1.2 P_SMA_BOT_2IN_DP_1.3 P_SMA_BOT_2IN_DP_1.4 P_SMA_BOT_2IN_DP_1.5 P_SMA_BOT_2IN_DP_1.6 P_SMA_BOT_2IN_DP_2.2 P_SMA_BOT_2IN_DP_2.3 P_SMA_BOT_2IN_DP_2.4 P_SMA_BOT_2IN_DP_2.5 P_SMA_BOT_2IN_DP_2.6 P_SMA_BOT_5IN_DN_1.2 P_SMA_BOT_5IN_DN_1.3 P_SMA_BOT_5IN_DN_1.4 P_SMA_BOT_5IN_DN_1.5 P_SMA_BOT_5IN_DN_1.6 P_SMA_BOT_5IN_DN_2.2 P_SMA_BOT_5IN_DN_2.3 P_SMA_BOT_5IN_DN_2.4 P_SMA_BOT_5IN_DN_2.5 P_SMA_BOT_5IN_DN_2.6 P_SMA_BOT_5IN_DP_1.2 P_SMA_BOT_5IN_DP_1.3 P_SMA_BOT_5IN_DP_1.4 P_SMA_BOT_5IN_DP_1.5 P_SMA_BOT_5IN_DP_1.6 P_SMA_BOT_5IN_DP_2.2 P_SMA_BOT_5IN_DP_2.3 P_SMA_BOT_5IN_DP_2.4 P_SMA_BOT_5IN_DP_2.5 P_SMA_BOT_5IN_DP_2.6 P_SMA_BOT_10IN_DN_1.2 P_SMA_BOT_10IN_DN_1.3 P_SMA_BOT_10IN_DN_1.4 P_SMA_BOT_10IN_DN_1.5 P_SMA_BOT_10IN_DN_1.6 P_SMA_BOT_10IN_DN_2.2 P_SMA_BOT_10IN_DN_2.3 P_SMA_BOT_10IN_DN_2.4 P_SMA_BOT_10IN_DN_2.5 P_SMA_BOT_10IN_DN_2.6 P_SMA_BOT_10IN_DP_1.2 P_SMA_BOT_10IN_DP_1.3 P_SMA_BOT_10IN_DP_1.4 P_SMA_BOT_10IN_DP_1.5 P_SMA_BOT_10IN_DP_1.6 P_SMA_BOT_10IN_DP_2.2 P_SMA_BOT_10IN_DP_2.3 P_SMA_BOT_10IN_DP_2.4 P_SMA_BOT_10IN_DP_2.5 P_SMA_BOT_10IN_DP_2.6 P_SMA_TOP_2IN_DN_1.2 P_SMA_TOP_2IN_DN_1.3 P_SMA_TOP_2IN_DN_1.4 P_SMA_TOP_2IN_DN_1.5 P_SMA_TOP_2IN_DN_1.6 P_SMA_TOP_2IN_DN_2.2 P_SMA_TOP_2IN_DN_2.3 P_SMA_TOP_2IN_DN_2.4 P_SMA_TOP_2IN_DN_2.5 P_SMA_TOP_2IN_DN_2.6 P_SMA_TOP_2IN_DP_1.2 P_SMA_TOP_2IN_DP_1.3 P_SMA_TOP_2IN_DP_1.4 P_SMA_TOP_2IN_DP_1.5 P_SMA_TOP_2IN_DP_1.6 P_SMA_TOP_2IN_DP_2.2 P_SMA_TOP_2IN_DP_2.3 P_SMA_TOP_2IN_DP_2.4 P_SMA_TOP_2IN_DP_2.5 P_SMA_TOP_2IN_DP_2.6 P_SMA_TOP_5IN_DN_1.2 P_SMA_TOP_5IN_DN_1.3 P_SMA_TOP_5IN_DN_1.4 P_SMA_TOP_5IN_DN_1.5 P_SMA_TOP_5IN_DN_1.6 P_SMA_TOP_5IN_DN_2.2 P_SMA_TOP_5IN_DN_2.3 P_SMA_TOP_5IN_DN_2.4 P_SMA_TOP_5IN_DN_2.5 P_SMA_TOP_5IN_DN_2.6 P_SMA_TOP_5IN_DP_1.2 P_SMA_TOP_5IN_DP_1.3 P_SMA_TOP_5IN_DP_1.4 P_SMA_TOP_5IN_DP_1.5 P_SMA_TOP_5IN_DP_1.6 P_SMA_TOP_5IN_DP_2.2 P_SMA_TOP_5IN_DP_2.3 P_SMA_TOP_5IN_DP_2.4 P_SMA_TOP_5IN_DP_2.5 P_SMA_TOP_5IN_DP_2.6 P_SMA_TOP_10IN_DN_1.2 P_SMA_TOP_10IN_DN_1.3 P_SMA_TOP_10IN_DN_1.4 P_SMA_TOP_10IN_DN_1.5 P_SMA_TOP_10IN_DN_1.6 P_SMA_TOP_10IN_DN_2.2 P_SMA_TOP_10IN_DN_2.3 P_SMA_TOP_10IN_DN_2.4 P_SMA_TOP_10IN_DN_2.5 P_SMA_TOP_10IN_DN_2.6 P_SMA_TOP_10IN_DP_1.2 P_SMA_TOP_10IN_DP_1.3 P_SMA_TOP_10IN_DP_1.4 P_SMA_TOP_10IN_DP_1.5 P_SMA_TOP_10IN_DP_1.6 P_SMA_TOP_10IN_DP_2.2 P_SMA_TOP_10IN_DP_2.3 P_SMA_TOP_10IN_DP_2.4 P_SMA_TOP_10IN_DP_2.5 P_SMA_TOP_10IN_DP_2.6
GND_BD2: BD2_P_OCP_CPU_0_N.2(MH1) BD2_P_OCP_CPU_0_N.3(MH2) BD2_P_OCP_CPU_0_N.4(MH3) BD2_P_OCP_CPU_0_N.5(MH4) BD2_P_OCP_CPU_0_N.6(MH6) BD2_P_OCP_CPU_0_P.2(MH1) BD2_P_OCP_CPU_0_P.3(MH2) BD2_P_OCP_CPU_0_P.4(MH3) BD2_P_OCP_CPU_0_P.5(MH4) BD2_P_OCP_CPU_0_P.6(MH6) C75.2 C76.1 C77.1 C78.1 C79.1 C80.2 C81.2 C82.1 C83.1 C84.2 C85.2 C87.1 C88.2 C89.1 C156.1 C158.1 C165.1 C167.2 DS_BD2_PWR.2(C) P7.2 P8.2 P9.2 P15.2 P_BD2_CLK0_N.2 P_BD2_CLK0_N.3 P_BD2_CLK0_N.4 P_BD2_CLK0_N.5 P_BD2_CLK0_N.6 P_BD2_CLK0_P.2 P_BD2_CLK0_P.3 P_BD2_CLK0_P.4 P_BD2_CLK0_P.5 P_BD2_CLK0_P.6 P_BD2_CLK1_N.2(MH1) P_BD2_CLK1_N.3(MH2) P_BD2_CLK1_N.4(MH3) P_BD2_CLK1_N.5(MH4) P_BD2_CLK1_N.6(MH6) P_BD2_CLK1_P.2(MH1) P_BD2_CLK1_P.3(MH2) P_BD2_CLK1_P.4(MH3) P_BD2_CLK1_P.5(MH4) P_BD2_CLK1_P.6(MH6) P_BD2_CLK2_N.2 P_BD2_CLK2_N.3 P_BD2_CLK2_N.4 P_BD2_CLK2_N.5 P_BD2_CLK2_N.6 P_BD2_CLK2_P.2 P_BD2_CLK2_P.3 P_BD2_CLK2_P.4 P_BD2_CLK2_P.5 P_BD2_CLK2_P.6 P_BD2_CMTS_N.2 P_BD2_CMTS_N.3 P_BD2_CMTS_N.4 P_BD2_CMTS_N.5 P_BD2_CMTS_N.6 P_BD2_CMTS_P.2 P_BD2_CMTS_P.3 P_BD2_CMTS_P.4 P_BD2_CMTS_P.5 P_BD2_CMTS_P.6 P_BD2_TRIG_IN_N.2(MH1) P_BD2_TRIG_IN_N.3(MH2) P_BD2_TRIG_IN_N.4(MH3) P_BD2_TRIG_IN_N.5(MH4) P_BD2_TRIG_IN_N.6(MH6) P_BD2_TRIG_IN_P.2(MH1) P_BD2_TRIG_IN_P.3(MH2) P_BD2_TRIG_IN_P.4(MH3) P_BD2_TRIG_IN_P.5(MH4) P_BD2_TRIG_IN_P.6(MH6) P_CPU_OCP_8_N.2 P_CPU_OCP_8_N.3 P_CPU_OCP_8_N.4 P_CPU_OCP_8_N.5 P_CPU_OCP_8_N.6 P_CPU_OCP_8_P.2 P_CPU_OCP_8_P.3 P_CPU_OCP_8_P.4 P_CPU_OCP_8_P.5 P_CPU_OCP_8_P.6 P_CPU_OCP_9_N.2 P_CPU_OCP_9_N.3 P_CPU_OCP_9_N.4 P_CPU_OCP_9_N.5 P_CPU_OCP_9_N.6 P_CPU_OCP_9_P.2 P_CPU_OCP_9_P.3 P_CPU_OCP_9_P.4 P_CPU_OCP_9_P.5 P_CPU_OCP_9_P.6 P_CPU_OCP_10_N.2 P_CPU_OCP_10_N.3 P_CPU_OCP_10_N.4 P_CPU_OCP_10_N.5 P_CPU_OCP_10_N.6 P_CPU_OCP_10_P.2 P_CPU_OCP_10_P.3 P_CPU_OCP_10_P.4 P_CPU_OCP_10_P.5 P_CPU_OCP_10_P.6 P_CPU_OCP_11_N.2 P_CPU_OCP_11_N.3 P_CPU_OCP_11_N.4 P_CPU_OCP_11_N.5 P_CPU_OCP_11_N.6 P_CPU_OCP_11_P.2 P_CPU_OCP_11_P.3 P_CPU_OCP_11_P.4 P_CPU_OCP_11_P.5 P_CPU_OCP_11_P.6 P_CPU_OCP_12_N.2 P_CPU_OCP_12_N.3 P_CPU_OCP_12_N.4 P_CPU_OCP_12_N.5 P_CPU_OCP_12_N.6 P_CPU_OCP_12_P.2 P_CPU_OCP_12_P.3 P_CPU_OCP_12_P.4 P_CPU_OCP_12_P.5 P_CPU_OCP_12_P.6 P_CPU_OCP_13_N.2 P_CPU_OCP_13_N.3 P_CPU_OCP_13_N.4 P_CPU_OCP_13_N.5 P_CPU_OCP_13_N.6 P_CPU_OCP_13_P.2 P_CPU_OCP_13_P.3 P_CPU_OCP_13_P.4 P_CPU_OCP_13_P.5 P_CPU_OCP_13_P.6 P_CPU_OCP_14_N.2 P_CPU_OCP_14_N.3 P_CPU_OCP_14_N.4 P_CPU_OCP_14_N.5 P_CPU_OCP_14_N.6 P_CPU_OCP_14_P.2 P_CPU_OCP_14_P.3 P_CPU_OCP_14_P.4 P_CPU_OCP_14_P.5 P_CPU_OCP_14_P.6 P_CPU_OCP_15_N.2 P_CPU_OCP_15_N.3 P_CPU_OCP_15_N.4 P_CPU_OCP_15_N.5 P_CPU_OCP_15_N.6 P_CPU_OCP_15_P.2 P_CPU_OCP_15_P.3 P_CPU_OCP_15_P.4 P_CPU_OCP_15_P.5 P_CPU_OCP_15_P.6 P_OCP_CPU_8_N.2(MH1) P_OCP_CPU_8_N.3(MH2) P_OCP_CPU_8_N.4(MH3) P_OCP_CPU_8_N.5(MH4) P_OCP_CPU_8_N.6(MH6) P_OCP_CPU_8_P.2(MH1) P_OCP_CPU_8_P.3(MH2) P_OCP_CPU_8_P.4(MH3) P_OCP_CPU_8_P.5(MH4) P_OCP_CPU_8_P.6(MH6) P_OCP_CPU_9_N.2(MH1) P_OCP_CPU_9_N.3(MH2) P_OCP_CPU_9_N.4(MH3) P_OCP_CPU_9_N.5(MH4) P_OCP_CPU_9_N.6(MH6) P_OCP_CPU_9_P.2(MH1) P_OCP_CPU_9_P.3(MH2) P_OCP_CPU_9_P.4(MH3) P_OCP_CPU_9_P.5(MH4) P_OCP_CPU_9_P.6(MH6) P_OCP_CPU_10_N.2(MH1) P_OCP_CPU_10_N.3(MH2) P_OCP_CPU_10_N.4(MH3) P_OCP_CPU_10_N.5(MH4) P_OCP_CPU_10_N.6(MH6) P_OCP_CPU_10_P.2(MH1) P_OCP_CPU_10_P.3(MH2) P_OCP_CPU_10_P.4(MH3) P_OCP_CPU_10_P.5(MH4) P_OCP_CPU_10_P.6(MH6) P_OCP_CPU_11_N.2(MH1) P_OCP_CPU_11_N.3(MH2) P_OCP_CPU_11_N.4(MH3) P_OCP_CPU_11_N.5(MH4) P_OCP_CPU_11_N.6(MH6) P_OCP_CPU_11_P.2(MH1) P_OCP_CPU_11_P.3(MH2) P_OCP_CPU_11_P.4(MH3) P_OCP_CPU_11_P.5(MH4) P_OCP_CPU_11_P.6(MH6) P_OCP_CPU_12_N.2(MH1) P_OCP_CPU_12_N.3(MH2) P_OCP_CPU_12_N.4(MH3) P_OCP_CPU_12_N.5(MH4) P_OCP_CPU_12_N.6(MH6) P_OCP_CPU_12_P.2(MH1) P_OCP_CPU_12_P.3(MH2) P_OCP_CPU_12_P.4(MH3) P_OCP_CPU_12_P.5(MH4) P_OCP_CPU_12_P.6(MH6) P_OCP_CPU_13_N.2(MH1) P_OCP_CPU_13_N.3(MH2) P_OCP_CPU_13_N.4(MH3) P_OCP_CPU_13_N.5(MH4) P_OCP_CPU_13_N.6(MH6) P_OCP_CPU_13_P.2(MH1) P_OCP_CPU_13_P.3(MH2) P_OCP_CPU_13_P.4(MH3) P_OCP_CPU_13_P.5(MH4) P_OCP_CPU_13_P.6(MH6) P_OCP_CPU_14_N.2(MH1) P_OCP_CPU_14_N.3(MH2) P_OCP_CPU_14_N.4(MH3) P_OCP_CPU_14_N.5(MH4) P_OCP_CPU_14_N.6(MH6) P_OCP_CPU_14_P.2(MH1) P_OCP_CPU_14_P.3(MH2) P_OCP_CPU_14_P.4(MH3) P_OCP_CPU_14_P.5(MH4) P_OCP_CPU_14_P.6(MH6) P_OCP_CPU_15_N.2(MH1) P_OCP_CPU_15_N.3(MH2) P_OCP_CPU_15_N.4(MH3) P_OCP_CPU_15_N.5(MH4) P_OCP_CPU_15_N.6(MH6) P_OCP_CPU_15_P.2(MH1) P_OCP_CPU_15_P.3(MH2) P_OCP_CPU_15_P.4(MH3) P_OCP_CPU_15_P.5(MH4) P_OCP_CPU_15_P.6(MH6) Q3.2(S) SW3.2 U17.3(GND) U18.3(GND) U19.3(GND) U20.1(GND) U21.3(GND) U22.3(GND) U23.3(GND) U25.9(GND) U25.17(EPAD) U27.3(GND) ; also on sheet 7
GND_SIGNAL: J_S2D_BOT.1(GND) J_S2D_TOP.1(GND) Z_42.5_BOT.1(RX) Z_42.5_BOT.3(RY) Z_42.5_BOT_END.1 Z_42.5_BOT_END.3 Z_42.5_TOP.1(RX) Z_42.5_TOP.3(RY) Z_42.5_TOP_END.1 Z_42.5_TOP_END.3 Z_85D_BOT.1(RX) Z_85D_BOT.3(RY) Z_85D_BOT_END.1 Z_85D_BOT_END.4 Z_85D_TOP.1(RX) Z_85D_TOP.3(RY) Z_85D_TOP_END.1 Z_85D_TOP_END.4 Z_100D_BOT.1(RX) Z_100D_BOT.3(RY) Z_100D_BOT_END.1 Z_100D_BOT_END.4 Z_100D_TOP.1(RX) Z_100D_TOP.3(RY) Z_100D_TOP_END.1 Z_100D_TOP_END.4
BD2_555_DISCHARGE: C80.1 R88.1 R89.1 U20.6(THRESHOLD) U20.7(DISCHARGE)
BD2_555_OUT: R93.2 R95.2 U20.3(OUT)
BD2_555_OUT_JP: P9.1 R93.1
BD2_555_RST_N: C81.1 R92.1 U20.4(RESET_N)
BD2_555_TRI: R85.2 R91.2 U20.2(TRIGGER_N)
BD2_BTN_NC: R84.1 R86.1 SW3.1 U17.1(A)
BD2_BTN_NO: R85.1 R94.1 SW3.3 U22.2(B)
BD2_BUS_SEL: C165.2 P15.1 Q3.1(G) R84.2 R95.1 R160.1 U27.2(A)
BD2_PE_OCP_CPU_0_DN: BD2_P_OCP_CPU_0_N.1 ; also on sheet 7
BD2_PE_OCP_CPU_0_DP: BD2_P_OCP_CPU_0_P.1 ; also on sheet 7
BD2_REFCLK0_DN: P_BD2_CLK0_N.1 ; also on sheet 7
BD2_REFCLK0_DP: P_BD2_CLK0_P.1 ; also on sheet 7
BD2_REFCLK1_DN: P_BD2_CLK1_N.1 ; also on sheet 7
BD2_REFCLK1_DP: P_BD2_CLK1_P.1 ; also on sheet 7
BD2_REFCLK2_DN: P_BD2_CLK2_N.1 ; also on sheet 7
BD2_REFCLK2_DP: P_BD2_CLK2_P.1 ; also on sheet 7
CLK2_HOST_TO_TRIGGER_DN: C158.2 P_BD2_TRIG_IN_N.1 U25.2(IN_n)
CLK2_HOST_TO_TRIGGER_DP: C156.2 P_BD2_TRIG_IN_P.1 U25.1(IN_p)
CLK2_TRIG_SIGNAL_C_DN: C90.1 R99.1
CLK2_TRIG_SIGNAL_C_DP: C86.1 R96.1
CLK2_TRIG_SIGNAL_DN: C90.2 U25.11(OUT0_n)
CLK2_TRIG_SIGNAL_DP: C86.2 U25.10(OUT0_p)
CLK2_TRIG_SIGNAL_R_DN: P_BD2_CMTS_N.1 R99.2
CLK2_TRIG_SIGNAL_R_DP: P_BD2_CMTS_P.1 R96.2
PE_CAL_BOT_OCP_CPU_0_DN: P_CAL_OCP_CPU_B_0_N.1 P_OCPSTRDL.A17
PE_CAL_BOT_OCP_CPU_0_DP: P_CAL_OCP_CPU_B_0_P.1 P_OCPSTRDL.A18
PE_CAL_CPU_OCP_0_DN: P_CAL_CPU_OCP_0_N1.1 P_OCPSTRDL.B17
PE_CAL_CPU_OCP_0_DP: P_CAL_CPU_OCP_0_P1.1 P_OCPSTRDL.B18
PE_CPU_OCP_8_DN: P_CPU_OCP_8_N.1 ; also on sheet 7
PE_CPU_OCP_8_DP: P_CPU_OCP_8_P.1 ; also on sheet 7
PE_CPU_OCP_9_DN: P_CPU_OCP_9_N.1 ; also on sheet 7
PE_CPU_OCP_9_DP: P_CPU_OCP_9_P.1 ; also on sheet 7
PE_CPU_OCP_10_DN: P_CPU_OCP_10_N.1 ; also on sheet 7
PE_CPU_OCP_10_DP: P_CPU_OCP_10_P.1 ; also on sheet 7
PE_CPU_OCP_11_DN: P_CPU_OCP_11_N.1 ; also on sheet 7
PE_CPU_OCP_11_DP: P_CPU_OCP_11_P.1 ; also on sheet 7
PE_CPU_OCP_12_DN: P_CPU_OCP_12_N.1 ; also on sheet 7
PE_CPU_OCP_12_DP: P_CPU_OCP_12_P.1 ; also on sheet 7
PE_CPU_OCP_13_DN: P_CPU_OCP_13_N.1 ; also on sheet 7
PE_CPU_OCP_13_DP: P_CPU_OCP_13_P.1 ; also on sheet 7
PE_CPU_OCP_14_DN: P_CPU_OCP_14_N.1 ; also on sheet 7
PE_CPU_OCP_14_DP: P_CPU_OCP_14_P.1 ; also on sheet 7
PE_CPU_OCP_15_DN: P_CPU_OCP_15_N.1 ; also on sheet 7
PE_CPU_OCP_15_DP: P_CPU_OCP_15_P.1 ; also on sheet 7
PE_OCP_CPU_8_DN: P_OCP_CPU_8_N.1 ; also on sheet 7
PE_OCP_CPU_8_DP: P_OCP_CPU_8_P.1 ; also on sheet 7
PE_OCP_CPU_9_DN: P_OCP_CPU_9_N.1 ; also on sheet 7
PE_OCP_CPU_9_DP: P_OCP_CPU_9_P.1 ; also on sheet 7
PE_OCP_CPU_10_DN: P_OCP_CPU_10_N.1 ; also on sheet 7
PE_OCP_CPU_10_DP: P_OCP_CPU_10_P.1 ; also on sheet 7
PE_OCP_CPU_11_DN: P_OCP_CPU_11_N.1 ; also on sheet 7
PE_OCP_CPU_11_DP: P_OCP_CPU_11_P.1 ; also on sheet 7
PE_OCP_CPU_12_DN: P_OCP_CPU_12_N.1 ; also on sheet 7
PE_OCP_CPU_12_DP: P_OCP_CPU_12_P.1 ; also on sheet 7
PE_OCP_CPU_13_DN: P_OCP_CPU_13_N.1 ; also on sheet 7
PE_OCP_CPU_13_DP: P_OCP_CPU_13_P.1 ; also on sheet 7
PE_OCP_CPU_14_DN: P_OCP_CPU_14_N.1 ; also on sheet 7
PE_OCP_CPU_14_DP: P_OCP_CPU_14_P.1 ; also on sheet 7
PE_OCP_CPU_15_DN: P_OCP_CPU_15_N.1 ; also on sheet 7
PE_OCP_CPU_15_DP: P_OCP_CPU_15_P.1 ; also on sheet 7
SET2DIL_85_BOT: J_S2D_BOT.2 J_S2D_BOT.3
SET2DIL_85_TOP: J_S2D_TOP.2 J_S2D_TOP.3
SMA_2IN_BOT_DN: P_SMA_BOT_2IN_DN_1.1 P_SMA_BOT_2IN_DN_2.1
SMA_2IN_BOT_DP: P_SMA_BOT_2IN_DP_1.1 P_SMA_BOT_2IN_DP_2.1
SMA_2IN_TOP_DN: P_SMA_TOP_2IN_DN_1.1 P_SMA_TOP_2IN_DN_2.1
SMA_2IN_TOP_DP: P_SMA_TOP_2IN_DP_1.1 P_SMA_TOP_2IN_DP_2.1
SMA_5IN_BOT_DN: P_SMA_BOT_5IN_DN_1.1 P_SMA_BOT_5IN_DN_2.1
SMA_5IN_BOT_DP: P_SMA_BOT_5IN_DP_1.1 P_SMA_BOT_5IN_DP_2.1
SMA_5IN_TOP_DN: P_SMA_TOP_5IN_DN_1.1 P_SMA_TOP_5IN_DN_2.1
SMA_5IN_TOP_DP: P_SMA_TOP_5IN_DP_1.1 P_SMA_TOP_5IN_DP_2.1
SMA_10IN_BOT_DN: P_SMA_BOT_10IN_DN_1.1 P_SMA_BOT_10IN_DN_2.1
SMA_10IN_BOT_DP: P_SMA_BOT_10IN_DP_1.1 P_SMA_BOT_10IN_DP_2.1
SMA_10IN_TOP_DN: P_SMA_TOP_10IN_DN_1.1 P_SMA_TOP_10IN_DN_2.1
SMA_10IN_TOP_DP: P_SMA_TOP_10IN_DP_1.1 P_SMA_TOP_10IN_DP_2.1
V_3P3AUX_2: C75.1 C76.2 C77.2 C78.2 C79.2 C82.2 C83.2 C85.1 C87.2 C88.1 C89.2 C167.1 R86.2 R88.2 R89.2 R92.2 R94.2 R97.1 R160.2 R168.1 U17.5(VCC) U18.5(VCC) U19.5(VCC) U20.8(V+) U21.5(VCC) U22.5(VCC) U23.5(VCC) U25.13(VDD) U27.5(VCC) ; also on sheet 7
V_12V_2: C157.2 R156.2 ; also on sheet 7
Z_42.5_BOT: Z_42.5_BOT.2(+) Z_42.5_BOT_END.2
Z_42.5_TOP: Z_42.5_TOP.2(+) Z_42.5_TOP_END.2
Z_85D_BOT_DN: Z_85D_BOT.4(-) Z_85D_BOT_END.3
Z_85D_BOT_DP: Z_85D_BOT.2(+) Z_85D_BOT_END.2
Z_85D_TOP_DN: Z_85D_TOP.4(-) Z_85D_TOP_END.3
Z_85D_TOP_DP: Z_85D_TOP.2(+) Z_85D_TOP_END.2
Z_100D_BOT_DN: Z_100D_BOT.4(-) Z_100D_BOT_END.3
Z_100D_BOT_DP: Z_100D_BOT.2(+) Z_100D_BOT_END.2
Z_100D_TOP_DN: Z_100D_TOP.4(-) Z_100D_TOP_END.3
Z_100D_TOP_DP: Z_100D_TOP.2(+) Z_100D_TOP_END.2
N16815513: R90.1 U17.4(Y) U18.1(A) U19.1(A) U21.1(A) U21.2(B) U22.1(A)
N16815530: U18.2(B) U19.4(Y) U23.1(A)
N16815572: U19.2(B) U23.4(Y)
N16815630: C84.1 U21.4(Y) U23.2(B)
N16815728: R87.1 R91.1 U18.4(Y)
N16815771: P7.1 R87.2
N16816367: DS_BD2_PWR.1(A) R97.2
N16816677: P8.1 R90.2
N16816726: U17.2(B) U22.4(Y)
N16879387: DS_BD2_TRIG.1(A) R156.1
N16879389: C157.1 DS_BD2_TRIG.2(C) Q3.3(D)
N17129452: U25.12(OE0b) U27.4(Y)
N17130684: R168.2 U25.16(OE1b)

Not connected (* = marked no-connect by the designer): LBL4 1(NC); LBL5 1(NC); P_OCPSTRDL A7 A8 A9 A10 A11 A12 A14 A15 A20 A21 A23 A24 A26 A27 A30 A31 A33 A34 A36 A37 A39 A40 A42 A44 A45 A47 A48 A50 A51 A53 A54 A56 A57 A59 A60 A62 A63 A65 A66 A68 A69 A70 B1 B2 B3 B4 B5 B6 B7 B8 B9 B10 B11 B12 B14 B15 B20 B21 B23 B24 B26 B27 B30 B31 B33 B34 B36 B37 B39 B40 B42 B44 B45 B47 B48 B50 B51 B53 B54 B56 B57 B59 B60 B62 B63 B65 B66 B68 B69 B70 OCP_A1 OCP_A2 OCP_A3 OCP_A4 OCP_A5 OCP_A7 OCP_A8 OCP_A9 OCP_A11 OCP_A12 OCP_A14 OCP_B1 OCP_B2 OCP_B3 OCP_B4 OCP_B5 OCP_B6 OCP_B7 OCP_B8 OCP_B9 OCP_B11 OCP_B12 OCP_B14; U20 5(CNTRL_VLT)*; U25 3(NC_1)* 4(NC_2)* 5(NC_3)* 6(NC_4)* 7(NC_5)* 8(NC_6)* 14(OUT1_p)* 15(OUT1_n)*; U27 1(NC)*

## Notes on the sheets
sheet 8
- RSVD TEST
- Board 2 - Rx/Tx Lanes 8-15 (Cont.)
- CMTS OUT
- CMTS IN
- TRIG LED
- PWR LED
- INPUT REFCLKS
- ROOM = BRD2
sheet 9
- Board 2 - Rx/Tx Lanes 8-15 (Cont.)
- CPU RX
- CPU TX
- ROOM = BRD2
sheet 10
- Board 2 - Rx/Tx Lanes 8-15 (Cont.)
- CPU RX
- CPU TX
- ROOM = BRD2
sheet 11
- SMAs (5 in and 10 in) - Breakaway Tab 2
- Impedance Coupons - Breakaway Tab 1
  ( 6 inches)
- SET 2 DIL Coupons - Breakaway Tab 1
- SMAs ( 2 in) - Breakaway Tab 2
sheet 12
- CLB CALIBRATION BOARD - Breakaway Tab 2
- CPU RX
- CPU TX
- ROOM = CAL
